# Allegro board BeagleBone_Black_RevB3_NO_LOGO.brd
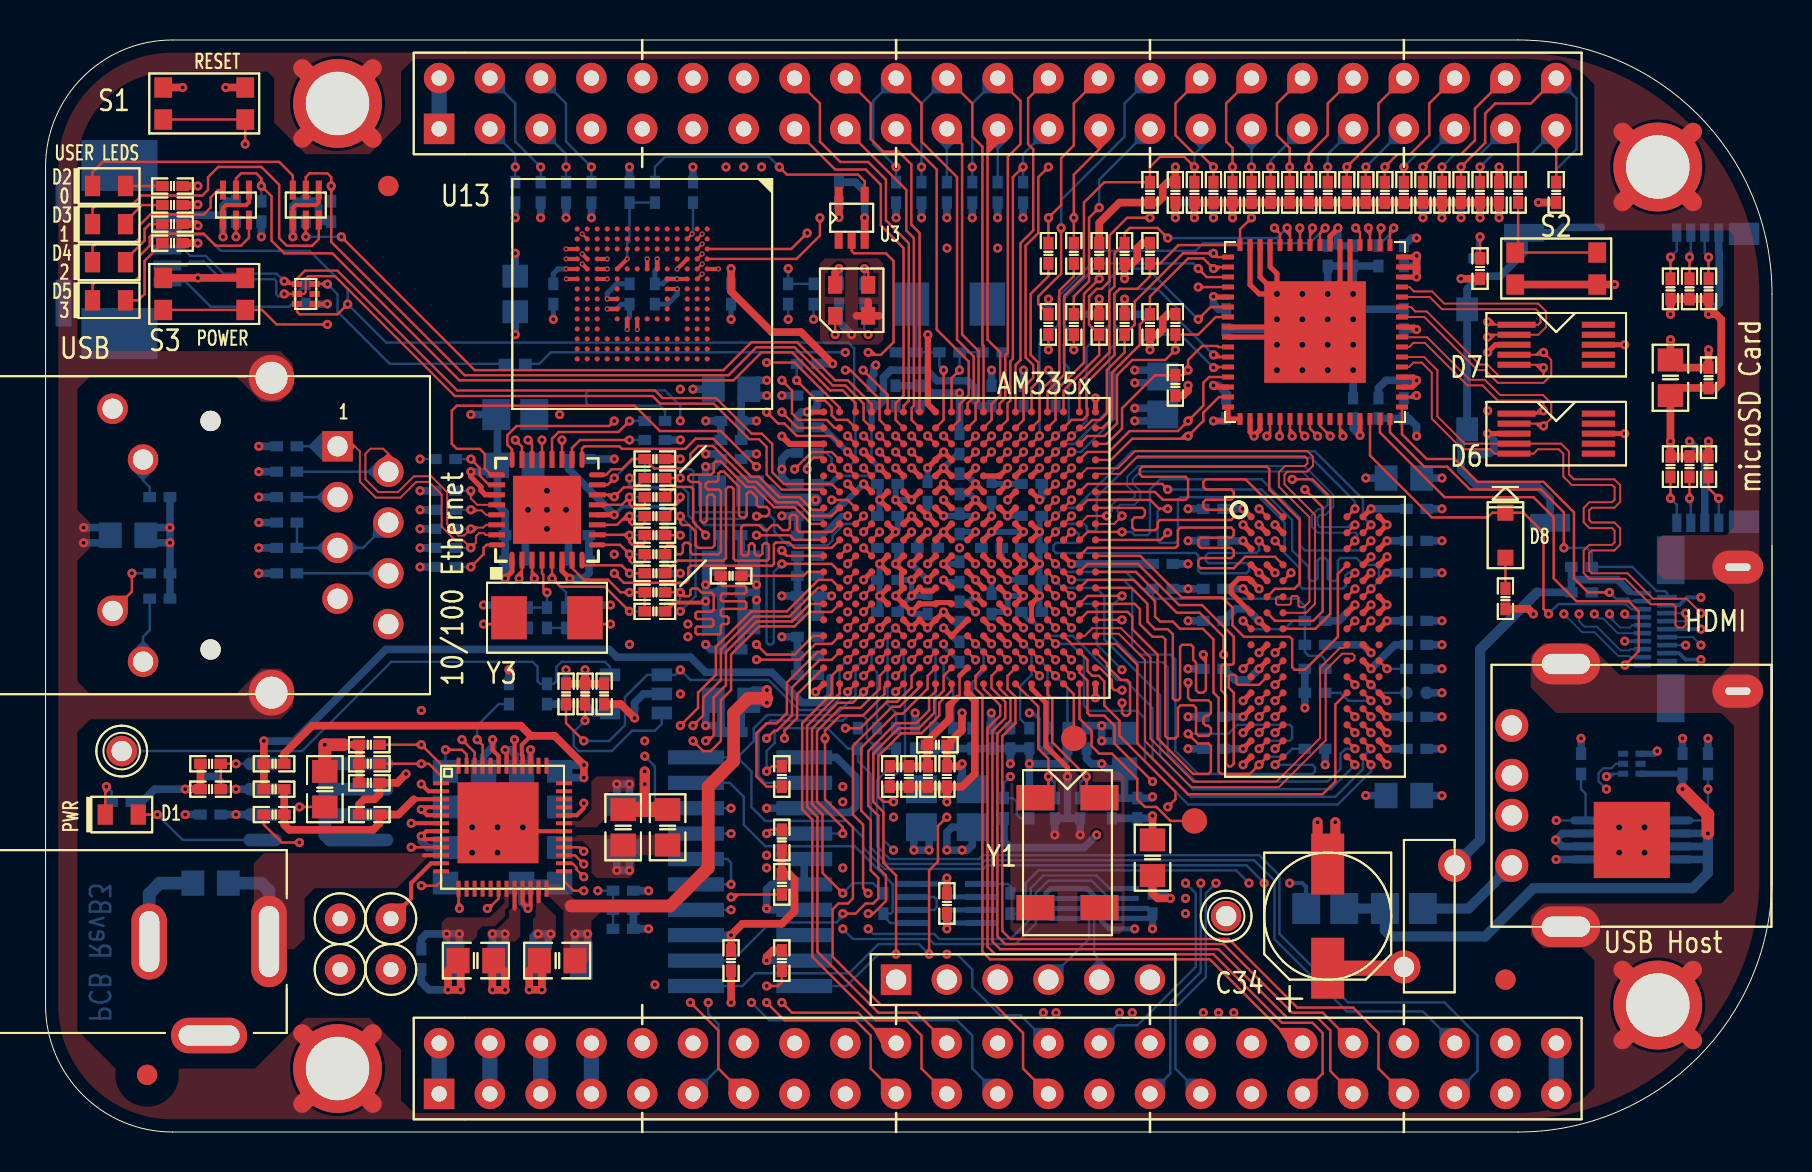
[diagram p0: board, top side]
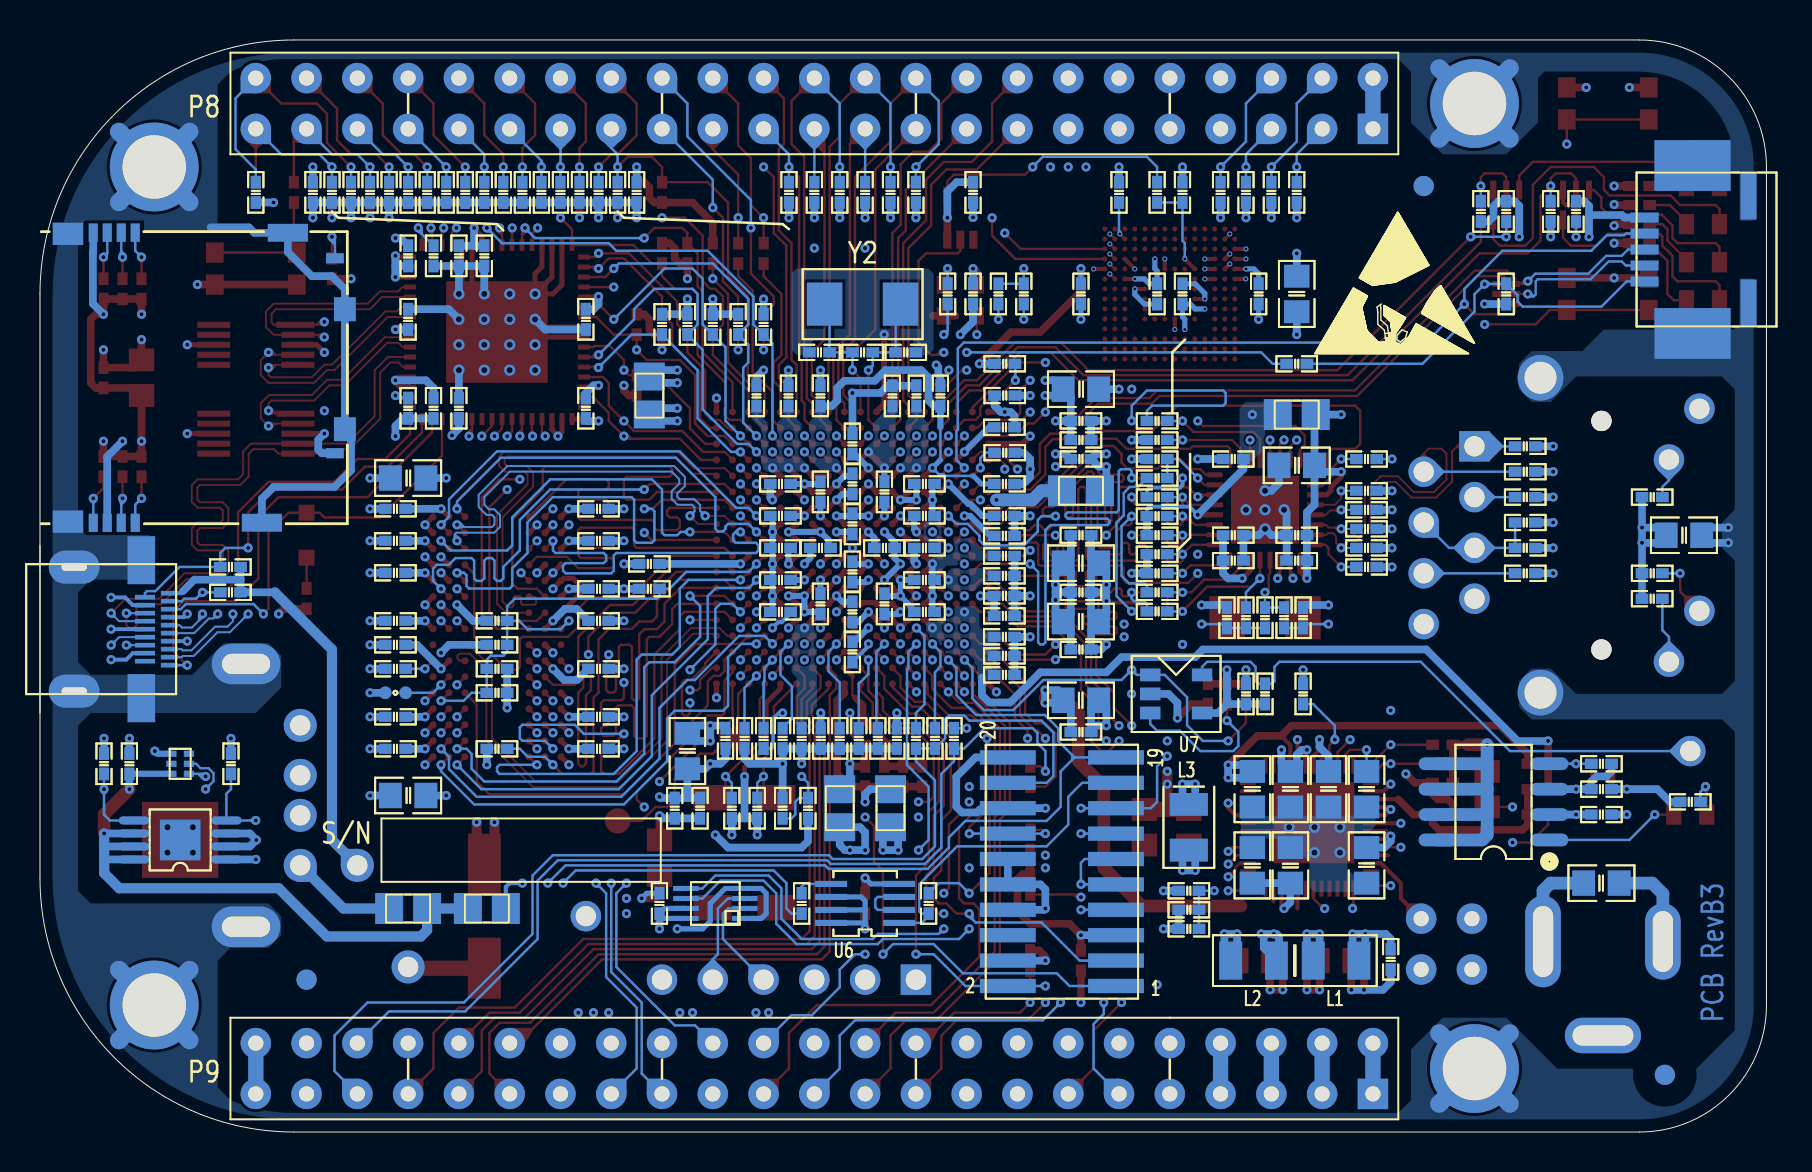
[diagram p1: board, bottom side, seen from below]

Outline 86.36 x 54.61 mm; copper layers: TOP, LYR2_GND, LYR3, LYR4, LYR5_PWR, BOTTOM. Coordinates in mm from the lower left corner of the outline.
Outline path: 0,48.26 0,6.35 arc(1.86,1.86) 6.35,0 73.66,0 arc(82.64,3.72) 86.36,12.7 86.36,41.91 arc(82.64,50.89) 73.66,54.61 6.35,54.61 arc(1.86,52.75) 0,48.26

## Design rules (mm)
net group HDMI_TX0: nets HDMI_TX0+ HDMI_TX0-
net group HDMI_TX1: nets HDMI_TX1+ HDMI_TX1-
net group HDMI_TX2: nets HDMI_TX2+ HDMI_TX2-
net group HDMI_TXC: nets HDMI_TXC+ HDMI_TXC-
net group RX: nets RXN RXP
net group TX: nets TXN TXP
net group USB0: nets USB0_DM USB0_DP
net group USB1: nets USB1_DM USB1_DP
net group CLK: nets MMC0_CLKO
net group DDR_ADD: nets DDR_A0 DDR_A1 DDR_A2 DDR_A3 DDR_A4 DDR_A5 DDR_A6 DDR_A7 DDR_A8 DDR_A9 DDR_A10 DDR_A11 DDR_A12 DDR_A13 DDR_A14 DDR_BA0 DDR_BA1 DDR_BA2 DDR_CASN DDR_CKE DDR_CLK DDR_CLKN DDR_CSN DDR_ODT DDR_RASN DDR_WEN
net group DDR_DQ0: nets DDR_D0 DDR_D1 DDR_D2 DDR_D3 DDR_D4 DDR_D5 DDR_D6 DDR_D7 DDR_DQM0 DDR_DQS0 DDR_DQSN0
net group DDR_DQ1: nets DDR_D8 DDR_D9 DDR_D10 DDR_D11 DDR_D12 DDR_D13 DDR_D14 DDR_D15 DDR_DQM1 DDR_DQS1 DDR_DQSN1
nets with their own width: min track width 0.203; nets USB1_VBUS

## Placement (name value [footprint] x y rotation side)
C1  10uF,10V  [805]  13.97 17.14 270 top
C2  10uF,10V  [805]  8.26 12.45 0 bottom
C3  0.1uf,6.3V  [402]  16.19 19.37 0 top
C4  10uF,10V  [805]  20 17.14 90 bottom
C7  10uF,10V  [805]  23.81 13.34 270 bottom
C8  10uF,10V  [805]  25.72 13.34 270 bottom
C9  10uF,10V  [805]  21.53 8.57 180 top
C10  10uF,10V  [805]  20 13.34 90 bottom
C11  10uF,10V  [805]  28.89 15.24 270 top
C12  10uF,10V  [805]  25.59 8.57 0 top
C13  10uF,10V  [805]  23.81 17.14 90 bottom
C14  10uF,10V  [805]  25.72 17.14 90 bottom
C15  10uF,10V  [805]  21.91 17.14 90 bottom
C16  2.2uF,6.3V  [402]  16.19 17.46 180 top
C17  2.2uF,6.3V  [402]  8.26 15.88 180 bottom
C18  2.2uF,6.3V  [402]  16.19 18.41 180 top
C19  470pF,6.3V  [402]  8.26 18.41 180 top
C20  0.1uf,6.3V  [402]  8.26 17.14 180 bottom
C21  18pF,50V  [402]  50.48 16.19 90 bottom
C22  18pF,50V  [402]  51.75 16.19 90 bottom
C24  1uF,10V  [402]  28.89 11.11 0 bottom
C25  18pF,50V  [402]  47.37 38.99 0 bottom
C26  18pF,50V  [402]  43.05 38.99 180 bottom
C27  0.1uf,6.3V  [402]  45.09 11.43 90 top
C28  0.1uf,6.3V  [402]  55.88 27.17 0 bottom
C29  0.1uf,6.3V  [402]  34.29 8.57 270 top
C30  0.1uf,6.3V  [402]  28.89 10.16 0 bottom
C31  0.1uf,6.3V  [402]  43.18 17.78 270 top
C32  0.001uf,50V  [402]  42.23 17.78 270 top
C33  0.1uf,6.3V  [402]  44.13 17.78 270 top
C34  100uF,6.3V  [RD205SMD_250D]  64.14 10.79 90 top
C35  0.1uf,6.3V  [402]  81.89 18.41 90 bottom
C36  0.1uf,6.3V  [402]  13.02 41.91 270 bottom
C37  0.1uf,6.3V  [402]  27.94 21.91 270 top
C38  0.1uf,6.3V  [402]  34.29 34.61 180 bottom
C39  10uF,10V  [805]  34.29 25.53 0 bottom
C40  10uF,10V  [805]  34.29 28.45 0 bottom
C41  0.1uf,6.3V  [402]  42.12 32.41 180 bottom
C42  0.1uf,6.3V  [402]  45.72 32.41 270 bottom
C43  0.1uf,6.3V  [402]  47.32 32.01 90 bottom
C44  0.1uf,6.3V  [402]  38.12 25.81 180 bottom
C45  0.1uf,6.3V  [402]  38.12 29.81 180 bottom
C46  0.1uf,6.3V  [402]  44.12 29.21 0 bottom
C47  0.1uf,6.3V  [402]  45.72 30.41 270 bottom
C48  0.1uf,6.3V  [402]  47.32 29.21 0 bottom
C49  0.1uf,6.3V  [402]  45.72 28.01 90 bottom
C50  0.1uf,6.3V  [402]  47.32 26.41 90 bottom
C51  0.1uf,6.3V  [402]  34.29 29.84 180 bottom
C52  0.1uf,6.3V  [402]  34.29 26.99 180 bottom
C53  0.1uf,6.3V  [402]  34.29 24.13 180 bottom
C54  0.1uf,6.3V  [402]  38.12 26.81 180 bottom
C55  10uF,10V  [805]  31.11 15.24 270 top
C56  0.1uf,6.3V  [402]  45.72 34.41 270 bottom
C57  0.1uf,6.3V  [402]  56.52 46.99 270 top
C58  0.1uf,6.3V  [402]  42.52 36.81 90 bottom
C59  0.1uf,6.3V  [402]  43.5 19.68 270 bottom
C60  0.1uf,6.3V  [402]  42.12 27.61 180 bottom
C61  0.1uf,6.3V  [402]  72.71 46.99 270 top
C62  10uF,10V  [805]  34.29 21.59 0 bottom
C63  0.1uf,6.3V  [402]  44.12 26.41 90 bottom
C64  0.1uf,6.3V  [402]  34.29 20 180 bottom
C65  0.1uf,6.3V  [402]  42.12 29.21 180 bottom
C66  0.1uf,6.3V  [402]  42.12 30.81 180 bottom
C67  0.1uf,6.3V  [402]  34.29 35.56 180 bottom
C68  0.1uf,6.3V  [402]  48.92 36.81 270 bottom
C69  0.1uf,6.3V  [402]  38.12 28.81 0 bottom
C70  0.1uf,6.3V  [402]  42.12 26.01 180 bottom
C71  0.1uf,6.3V  [402]  38.1 36.83 180 bottom
C72  0.1uf,6.3V  [402]  45.72 26.01 270 bottom
C73  0.1uf,6.3V  [402]  49.32 32.41 0 bottom
C74  0.1uf,6.3V  [402]  50.52 36.81 270 bottom
C75  0.1uf,6.3V  [402]  56.52 46.99 270 bottom
C76  0.1uf,6.3V  [402]  72.71 46.99 270 bottom
C77  10uF,10V  [805]  34.29 37.15 180 bottom
C78  0.1uf,6.3V  [402]  34.29 33.66 0 bottom
C79  0.1uf,6.3V  [402]  38.12 27.81 180 bottom
C80  0.1uf,6.3V  [402]  41.32 36.81 90 bottom
C81  0.1uf,6.3V  [402]  47.32 36.81 90 bottom
C82  0.1uf,6.3V  [402]  38.12 24.77 180 bottom
C83  0.1uf,6.3V  [402]  38.12 23.81 180 bottom
C84  0.1uf,6.3V  [402]  38.12 32.41 180 bottom
C85  0.1uf,6.3V  [402]  38.12 22.86 180 bottom
C86  0.1uf,6.3V  [402]  38.12 35.24 180 bottom
C87  0.1uf,6.3V  [402]  38.12 30.81 180 bottom
C88  0.1uf,6.3V  [402]  45.72 24.01 270 bottom
C89  1uF,10V  [402]  46.35 19.68 270 bottom
C90  1uF,10V  [402]  44.45 19.68 270 bottom
C91  1uF,10V  [402]  45.4 19.68 270 bottom
C92  0.1uf,6.3V  [402]  48.26 19.68 270 bottom
C93  0.1uf,6.3V  [402]  45.09 17.78 270 top
C94  0.1uf,6.3V  [402]  44.12 32.01 270 bottom
C95  10uF,10V  [805]  53.98 19.05 90 bottom
C96  10uF,10V  [805]  55.37 13.72 90 top
C97  0.1uf,6.3V  [402]  49.32 30.81 180 bottom
C98  0.1uf,6.3V  [402]  49.32 29.21 180 bottom
C99  0.1uf,6.3V  [402]  49.32 27.61 180 bottom
C100  0.1uf,6.3V  [402]  49.32 26.01 180 bottom
C101  0.1uf,6.3V  [402]  52.07 19.68 270 bottom
C102  0.1uf,6.3V  [402]  53.34 16.19 90 bottom
C103  0.1uf,6.3V  [402]  54.61 16.19 90 bottom
C104  1uF,10V  [402]  49.21 19.68 270 bottom
C105  0.1uf,6.3V  [402]  47.31 19.68 270 bottom
C106  0.1uf,6.3V  [402]  43.72 36.81 90 bottom
C107  0.1uf,6.3V  [402]  58.42 31.17 180 bottom
C108  0.1uf,6.3V  [402]  58.42 29.57 180 bottom
C109  0.1uf,6.3V  [402]  58.42 27.17 180 bottom
C110  0.1uf,6.3V  [402]  58.42 25.57 180 bottom
C111  0.1uf,6.3V  [402]  58.42 23.16 180 bottom
C112  0.1uf,6.3V  [402]  58.42 20.76 180 bottom
C113  0.1uf,6.3V  [402]  58.42 19.16 180 bottom
C114  0.1uf,6.3V  [402]  68.58 31.17 0 bottom
C115  0.1uf,6.3V  [402]  68.58 29.57 0 bottom
C116  0.1uf,6.3V  [402]  68.58 27.97 0 bottom
C117  0.1uf,6.3V  [402]  68.58 25.57 0 bottom
C118  10uF,10V  [805]  67.94 32.7 180 bottom
C119  0.1uf,6.3V  [402]  68.58 24.36 0 bottom
C120  0.1uf,6.3V  [402]  68.58 20.76 0 bottom
C121  0.1uf,6.3V  [402]  68.58 19.16 0 bottom
C122  10uF,10V  [805]  67.94 16.83 180 bottom
C123  0.001uf,50V  [402]  63.5 24.36 0 bottom
C124  0.1uf,6.3V  [402]  63.5 21.96 180 bottom
C125  2.2uF,6.3V  [402]  32.38 46.99 90 bottom
C126  10uF,10V  [805]  23.5 41.91 90 bottom
C127  0.1uf,6.3V  [402]  25.4 41.91 270 bottom
C128  0.1uf,6.3V  [402]  29.21 41.91 90 bottom
C129  0.1uf,6.3V  [402]  30.48 41.91 270 bottom
C130  0.1uf,6.3V  [402]  34.29 41.91 270 bottom
C131  0.1uf,6.3V  [402]  23.5 28.57 0 bottom
C132  0.1uf,6.3V  [402]  23.5 29.84 0 bottom
C133  10uF,10V  [805]  23.5 33.34 180 bottom
C134  1uF,10V  [402]  26.67 28.57 180 bottom
C135  0.1uf,6.3V  [402]  26.67 33.66 0 bottom
C136  470pF,6.3V  [0402]  26.67 29.84 180 bottom
C137  15pF,DNI  [402]  12.06 34.29 180 bottom
C138  15pF,DNI  [402]  12.06 33.02 180 bottom
C139  15pF,DNI  [402]  12.06 31.75 180 bottom
C140  15pF,DNI  [402]  12.06 27.94 180 bottom
C141  0.022uF,10V  [402]  12.06 30.48 180 bottom
C142  30pF,50V  [402]  23.18 25.72 90 bottom
C143  30pF,50V  [402]  26.99 25.72 90 bottom
C144  2.2uF,6.3V  [402]  59.05 40.64 270 bottom
C145  0.1uf,6.3V  [402]  59.05 36.2 270 bottom
C146  2.2uF,6.3V  [402]  64.14 43.81 270 bottom
C147  0.1uf,6.3V  [402]  65.41 36.2 90 bottom
C148  2.2uF,6.3V  [402]  65.41 43.81 270 bottom
C149  0.1uf,6.3V  [402]  67.94 43.81 90 bottom
C150  0.1uf,6.3V  [402]  67.94 40.64 90 bottom
C151  2.2uF,6.3V  [402]  66.67 36.2 270 bottom
C152  0.1uf,6.3V  [402]  26.04 21.91 90 bottom
C153  10uF,10V  [805]  81.28 37.72 90 top
C154  0.1uf,6.3V  [402]  83.19 37.72 90 top
C155  0.1uf,6.3V  [402]  55.37 11.43 270 bottom
C156  47pf,6.3V  [402]  55.24 43.94 90 top
C157  47pf,6.3V  [402]  53.98 40.39 90 top
C158  0.1uf,6.3V  [402]  39.69 46.99 90 bottom
C159  0.1uf,6.3V  [402]  39.69 41.91 270 bottom
C160  47pf,6.3V  [402]  55.24 40.39 270 top
C161  47pf,6.3V  [402]  51.44 40.39 90 bottom
C162  47pf,6.3V  [402]  52.7 40.39 90 bottom
C163  47pf,6.3V  [402]  56.52 40.39 90 top
C164  47pf,6.3V  [402]  50.16 40.39 90 bottom
C165  47pf,6.3V  [402]  55.24 46.99 270 top
C166  47pf,6.3V  [402]  52.7 40.39 90 top
C167  47pf,6.3V  [402]  53.98 43.94 270 top
C168  47pf,6.3V  [402]  52.7 43.94 90 top
C169  47pf,6.3V  [402]  56.52 37.34 270 top
C170  47pf,6.3V  [402]  53.98 40.39 90 bottom
C171  47pf,6.3V  [402]  75.56 46.99 270 bottom
C172  47pf,6.3V  [402]  55.24 40.39 90 bottom
C173  47pf,6.3V  [402]  75.56 46.99 270 top
D1  LTST-C191TBKT  [LED_0603]  3.81 15.88 0 top
D2  LTST-C191TBKT  [LED_0603]  3.17 47.31 0 top
D3  LTST-C191TBKT  [LED_0603]  3.17 45.4 0 top
D4  LTST-C191TBKT  [LED_0603]  3.17 43.5 0 top
D5  LTST-C191TBKT  [LED_0603]  3.17 41.59 0 top
D6  IP4283CZ10-TT  [TSSOP10]  75.56 34.92 270 top
D7  IP4283CZ10-TT  [TSSOP10]  75.56 39.37 270 top
D8  RB751V40,115  [SOD323]  73.03 29.84 90 top
FB1  150OHM800mA  [SM-7351-IND-0805]  34.29 32.07 0 bottom
FB2  150OHM800mA  [SM-7351-IND-0805]  46.35 16.19 270 bottom
FB3  150OHM800mA  [SM-7351-IND-0805]  43.81 16.19 270 bottom
FB4  150OHM800mA  [SM-7351-IND-0805]  23.5 35.88 180 bottom
FB5  150OHM800mA  [SM-7351-IND-0805]  55.88 36.83 270 bottom
FB7  150OHM800mA  [SM-7351-IND-0805]  67.94 11.18 0 bottom
FB8  150OHM800mA  [SM-7351-IND-0805]  64.01 11.18 0 bottom
J1  HEADER 6  [SIP6]  42.55 7.62 90 top
L1  LQM2HPN2R2MG0L  [2520]  21.53 8.57 180 bottom
L2  LQM2HPN2R2MG0L  [2520]  25.65 8.57 0 bottom
L3  LQM2HPN2R2MG0L  [2520]  28.89 15.24 270 bottom
MTG1  MHOLE  [MTGH200C125D_PL]  14.61 3.17 90 top
MTG2  MHOLE  [MTGH200C125D_PL]  80.64 6.35 90 top
MTG3  MHOLE  [MTGH200C125D_PL]  14.61 51.44 90 top
MTG4  MHOLE  [MTGH200C125D_PL]  80.64 48.26 90 top
NOREF  -  []  85.72 28.57 0 top
NOREF#2  -  [unnamed#2]  17.14 47.31 270 top
NOREF#3  -  []  0 0 0 top
NOREF#4  -  []  86.36 39.69 0 top
NOREF#5  -  [unnamed#2]  5.08 2.86 270 top
NOREF#6  -  []  86.36 12.7 0 top
NOREF#7  -  [unnamed#2]  73.03 7.62 270 top
NOREF#8  -  []  319.53 -174.24 0 top
NOREF#9  -  []  80.64 48.26 0 top
NOREF#10  -  []  85.72 39.05 0 top
NOREF#11  -  []  80.64 6.35 0 top
NOREF#12  -  []  85.72 28.57 0 top
NOREF#13  -  []  81.92 52.07 0 top
NOREF#14  -  []  -11.96 0 90 top
NOREF#15  -  []  14.61 3.17 0 top
NOREF#16  -  []  86.36 27.94 0 top
NOREF#17  -  []  -368.3 -256.54 0 top
NOREF#18  -  []  6.35 54.61 0 top
NOREF#19  -  []  14.61 3.17 0 top
NOREF#20  -  []  0 -11.96 0 top
NOREF#21  -  []  -368.17 -256.47 0 top
NOREF#22  -  []  80.64 6.35 0 top
NOREF#23  -  []  -34.92 -47.62 0 top
NOREF#24  -  []  0 0 0 top
NOREF#25  -  []  14.61 51.44 0 top
NOREF#26  -  []  1.91 53.34 180 bottom
NOREF#27  -  [unnamed#2]  5.08 2.86 270 bottom
NOREF#28  -  [unnamed#2]  73.03 7.62 270 bottom
NOREF#29  -  [unnamed#2]  17.14 47.31 270 bottom
P1  PJ-200A  [CONN3-PWR-PJ102A]  11.18 9.53 180 top
P2  CTI JTAG,DNI  [HEADER10X2_SMD]  35.24 13.02 90 bottom
P3  USB-A Conn. - 87520-xx1xx  [USB_A_SH]  73.34 13.34 90 top
P4  USB5MINI  [USB5MINI_4SHIELDED_SMD-5]  6.1 44.13 0 bottom
P5  WE_7499010211A  [RJ45-7499010211A]  14.61 34.29 270 top
P6  microHDMI  [CONN19_HDMI]  84.65 25.15 270 bottom
P8  FEMALE HEADER 2x23  [HEADER23X2]  19.68 50.16 0 top
P9  FEMALE HEADER 2x23  [HEADER23X2]  19.68 1.91 0 top
P10  SCHA5B0200  [SD-MICRO-SCHA5B0300]  81.6 37.72 270 bottom
Q1  DMC56404  [SMINI6-F3-B]  13.02 46.35 180 top
Q2  DMC56404  [SMINI6-F3-B]  9.53 46.35 180 top
R1  100K,1%  [402]  23.18 21.91 270 bottom
R3  1.5K,5%  [402]  26.04 21.91 270 top
R4  1.5K,5%  [402]  26.99 21.91 270 top
R5  0  [402]  16.19 15.88 180 top
R6  0  [402]  18.8 8.64 270 bottom
R7  0  [402]  11.43 15.88 180 top
R8  0  [402]  11.43 17.14 180 top
R9  0,DNI  [402]  11.43 18.41 0 top
R10  470K,1%  [402]  8.26 17.14 180 top
R11  280K,1%  [402]  8.26 18.41 0 bottom
R12  820,5%  [402]  3.81 16.51 180 bottom
R14  10K,1%  [402]  28.89 12.06 180 bottom
R17  1M,1%  [402]  45.21 38.99 180 bottom
R18  33  [0402]  41.91 11.43 270 bottom
R19  0,1%  [402]  41.59 19.68 270 bottom
R20  0,1%  [402]  42.55 19.68 90 bottom
R21  33  [0402]  48.26 11.43 270 bottom
R22  49.9,1%  [402]  55.88 28.41 180 bottom
R23  4.75K,1%  [402]  36.83 12.38 270 top
R24  4.75K,1%  [402]  36.83 14.61 90 top
R25  4.75K,1%  [402]  36.83 8.57 90 top
R26  4.75K,1%  [402]  50.16 19.68 90 bottom
R27  0,1%  [402]  44.61 19.37 180 top
R28  33  [0402]  34.29 27.81 180 top
R45  33  [0402]  50.16 43.94 90 top
R46  33  [0402]  51.44 43.94 90 top
R47  33  [0402]  51.44 40.39 90 top
R48  33  [0402]  50.16 40.39 90 top
R49  0,1%  [402]  38.1 33.97 0 bottom
R50  0,1%  [402]  36.83 17.78 270 top
R51  0,1%  [402]  40.64 19.68 90 bottom
R52  10K,1%  [402]  83.16 18.41 270 bottom
R53  10K,1%  [402]  76.81 18.41 90 bottom
R54  10K,1%  [402]  51.12 19.68 90 bottom
R55  100K,1%,DNI  [402]  58.42 46.99 90 bottom
R56  100K,1%  [402]  57.47 46.99 90 bottom
R57  100K,1%,DNI  [402]  60.33 46.99 90 bottom
R58  100K,1%,DNI  [402]  61.28 46.99 90 bottom
R59  100K,1%,DNI  [402]  59.37 46.99 90 bottom
R60  100K,1%,DNI  [402]  62.23 46.99 90 bottom
R61  100K,1%,DNI  [402]  63.18 46.99 90 bottom
R62  100K,1%,DNI  [402]  64.14 46.99 90 bottom
R63  100K,1%,DNI  [402]  65.09 46.99 90 bottom
R64  100K,1%,DNI  [402]  66.04 46.99 90 bottom
R65  100K,1%  [402]  66.99 46.99 90 bottom
R66  100K,1%  [402]  67.94 46.99 90 bottom
R67  100K,1%  [402]  68.9 46.99 90 bottom
R68  100K,1%  [402]  69.85 46.99 90 bottom
R69  100K,1%,DNI  [402]  70.8 46.99 90 bottom
R70  100K,1%,DNI  [402]  71.75 46.99 90 bottom
R71  820,5%  [402]  6.35 44.45 180 top
R72  820,5%  [402]  6.35 47.31 180 top
R73  820,5%  [402]  6.35 46.35 180 top
R74  820,5%  [402]  6.35 45.4 180 top
R75  100  [402]  73.66 46.99 270 top
R76  100K,1%  [402]  13.02 46.04 90 bottom
R77  100K,1%  [402]  14.29 46.04 270 bottom
R78  100K,1%  [402]  9.53 46.04 90 bottom
R79  100K,1%  [402]  10.79 46.04 270 bottom
R80  100K,1%  [402]  58.42 46.99 270 top
R81  100K,1%,DNI  [402]  57.47 46.99 270 top
R82  100K,1%  [402]  60.33 46.99 270 top
R83  100K,1%  [402]  61.28 46.99 270 top
R84  100K,1%  [402]  59.37 46.99 270 top
R85  100K,1%  [402]  62.23 46.99 270 top
R86  100K,1%  [402]  63.18 46.99 270 top
R87  100K,1%  [402]  64.14 46.99 270 top
R88  100K,1%  [402]  65.09 46.99 270 top
R89  100K,1%  [402]  66.04 46.99 270 top
R90  100K,1%,DNI  [402]  66.99 46.99 270 top
R91  100K,1%,DNI  [402]  67.94 46.99 270 top
R92  100K,1%,DNI  [402]  68.9 46.99 270 top
R93  100K,1%,DNI  [402]  69.85 46.99 270 top
R94  100K,1%  [402]  70.8 46.99 270 top
R95  100K,1%  [402]  71.75 46.99 270 top
R96  10K,1%  [402]  68.58 23.16 180 bottom
R97  1.5K,1%  [402]  63.5 19.16 180 bottom
R98  10K,1%  [402]  63.5 25.57 180 bottom
R99  240E  [SM-7351-RES-0402]  68.58 21.96 180 bottom
R100  10K,1%  [402]  63.5 23.16 180 bottom
R101  10K,1%  [402]  48.9 46.99 90 bottom
R102  10K,1%  [402]  46.35 46.99 90 bottom
R103  10K,1%  [402]  26.04 46.99 90 bottom
R104  10K,1%  [402]  27.3 46.99 90 bottom
R105  10K,1%  [402]  47.62 46.99 90 bottom
R106  10K,1%  [402]  43.81 46.99 90 bottom
R107  10K,1%  [402]  23.5 46.99 90 bottom
R108  10K,1%  [402]  24.77 46.99 90 bottom
R109  10K,1%  [402]  42.55 46.99 90 bottom
R110  10K,1%  [402]  45.09 46.99 90 bottom
R111  10K,1%  [402]  29.21 46.99 270 bottom
R112  1.5K,1%  [402]  30.48 30.8 0 bottom
R113  1.5K,1%  [402]  30.48 33.66 0 bottom
R114  1.5K,1%  [402]  30.48 29.84 0 bottom
R115  10K,1%  [402]  30.48 31.75 0 bottom
R116  10K,1%  [402]  30.48 27.94 0 bottom
R117  10K,1%  [402]  30.48 28.89 0 bottom
R118  10K,1%  [402]  30.48 26.04 0 top
R119  1.5K,5%  [402]  30.48 33.66 180 top
R120  49.9,1%  [402]  20 29.21 180 bottom
R121  49.9,1%  [402]  20 30.16 180 bottom
R122  49.9,1%  [402]  20 31.11 180 bottom
R123  49.9,1%  [402]  20 32.07 180 bottom
R124  10,1%,DNI  [402]  30.48 26.99 180 top
R125  100,1%  [402]  30.48 27.94 180 top
R126  100,1%  [402]  30.48 28.89 180 top
R127  100,1%  [402]  30.48 29.84 180 top
R128  100,1%  [402]  30.48 30.8 180 top
R129  100,1%  [402]  20 33.66 0 bottom
R130  470,5%  [402]  5.71 27.94 180 bottom
R131  100,1%  [402]  30.48 26.99 180 bottom
R132  470,5%  [402]  5.71 31.75 180 bottom
R133  100,1%  [402]  30.48 31.75 180 top
R134  100,1%  [402]  30.48 35.56 180 bottom
R135  10K,1%  [402]  5.71 26.67 0 bottom
R136  .1,0805  [805]  4.13 29.84 180 bottom
R137  0,1%  [402]  12.06 29.21 180 bottom
R138  100,1%  [402]  30.48 32.7 180 bottom
R139  100,1%  [402]  30.48 32.7 180 top
R140  0,1%,DNI  [402]  30.48 26.04 180 bottom
R141  1M,1%,DNI  [402]  25.08 25.72 270 bottom
R142  0,1%  [402]  26.04 25.72 90 bottom
R143  10,1%  [402]  24.13 25.72 270 bottom
R144  12.1K,1%  [402]  20 28.26 180 bottom
R145  10K,1%  [402]  30.48 34.61 0 bottom
R146  1.5K,5%  [402]  76.83 26.99 0 bottom
R147  1.5K,5%  [402]  76.83 28.26 0 bottom
R148  10K,1%  [402]  67.94 36.2 270 bottom
R149  0,1%  [402]  66.67 43.81 270 bottom
R150  10K,1%  [402]  81.28 42.16 90 top
R151  10K,1%  [402]  83.19 42.16 90 top
R152  10K,1%  [402]  83.19 33.27 270 top
R153  10K,1%  [402]  82.23 33.27 270 top
R154  10K,1%  [402]  81.28 33.27 270 top
R155  10K,1%  [402]  82.23 42.16 90 top
R156  10K,1%  [402]  25.08 21.91 90 bottom
R157  10K,1%  [402]  71.75 43.18 270 top
R158  10K,1%  [402]  38.1 38.42 180 bottom
R159  0,1%  [402]  23.5 38.42 0 bottom
R160  0,1%  [402]  38.42 41.91 90 bottom
R161  0,1%  [402]  37.15 41.91 90 bottom
R162  0,1%  [402]  30.48 46.99 270 bottom
R163  4.75K,1%  [402]  47.94 16.19 90 bottom
R164  4.75K,1%  [402]  49.21 16.19 90 bottom
R166  27K,1%  [402]  73.03 26.67 270 top
R167  33  [0402]  40.96 41.91 270 bottom
RT1  PTC_RXEF010  [POLYSW200-5638-310]  70.48 13.34 90 top
S1  KMR231GLFS  [SW4SMD_63X161LS]  7.94 51.44 180 top
S2  KMR231GLFS  [SW4SMD_63X161LS]  75.56 43.18 180 top
S3  KMR231GLFS  [SW4SMD_63X161LS]  7.94 41.91 180 top
TP1  TESTPT1  [TP1-8040]  59.05 10.79 0 top
TP2  TESTPT1  [TP60C_SMD]  57.47 15.56 0 top
TP3  TESTPT1  [TP60C_SMD]  51.44 19.68 0 top
TP4  TESTPT1  [TP1-8040]  3.81 19.05 0 top
TP5  TESTPT1  [TP60C33D]  14.73 10.67 0 top
TP6  TESTPT1  [TP60C33D]  14.73 8.13 0 top
TP7  TESTPT1  [TP60C33D]  17.27 10.67 0 top
TP8  TESTPT1  [TP60C33D]  17.27 8.13 0 top
U2  TPS65217C  [U_48_RSL]  22.86 15.24 0 top
U3  SN74LVC1G06DCK  [DCK5_2P15X1P4]  40.32 45.72 0 top
U4  TL5209  [SO8-25X75]  13.65 16.51 90 bottom
U5  AM3358_ZCZ_ES1.0  [AM33XX_15X15]  45.72 29.21 180 top
U6  SN74AUC1G74  [SOP8_DCT]  45.09 11.43 90 bottom
U7  24LC32A  [SOT23-5]  29.53 21.91 270 bottom
U8  TPS2051 (DGN)  [DGN-16X60]  79.35 14.61 90 bottom
U9  TPD4S012  [U_6_DRY]  79.35 18.41 90 bottom
U10  TPD4S012  [U_6_DRY]  13.02 41.91 270 top
U11  TDA19988  [QFN64S9X9P5]  63.5 40.01 0 top
U12  MT41K256M16HA -125:E  [BGA96_T9_P8_9X14]  63.5 24.77 0 top
U13  MEM_MNAND_2GB  [BGA153_P14_P5_11P5X13]  29.84 41.91 270 top
U14  LAN8710A  [QFN32_5X5MM_EP3P3MM]  25.08 31.11 0 top
U15  SN74LVC2G241  [U_8_DCU]  52.58 11.43 90 bottom
Y1  32.768KHz MC-306  [XTAL4_126-216SMD]  51.12 13.97 270 top
Y2  24MHz  [XTAL150SMD_125X196]  45.21 41.4 0 bottom
Y3  25.000MHz  [XTAL150SMD_125X196]  25.08 25.72 180 top
Y4  24.576MHZ  [OSC4_61X65LS_79X98SMD]  40.32 41.59 0 top

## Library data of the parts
C1 C2 C4 C7-C15 C39 C40 C55 C62 C77 C95 C96 C118 C122 C126 C133 C153 = CAP_10uF_Y5V_10V_10%_0805
C3 C20 C27-C31 C33 C35-C38 C41-C54 C56-C61 C63-C76 C78-C88 C92-C94 C97-C103 C105-C117 C119-C121 C124 C127-C132 C135 C145 C147 C149 C150 C152 C154-C173 = CAP_0.1uF_X5R_6.3V_20% 0201
C16-C18 C125 C144 C146 C148 C151 = CAP_2.2uF_X5R_6.3V_10%_0402
C19 = CAP_470PF_X7R_25V_10%_0402
C21 C22 C25 C26 = CAP_18PF_COG_50V_5%_0402
C24 C89-C91 C104 C134 = CAP_1.0UF_X5R_10V_10%_0402
C32 C123 = CAP_0.001_X7R_50V_5%_0402
C34 = CAP_100UF_TANT_6.3V_3528-21
C136 = 470pF/5%/50V/C0G/0603_0
C137-C140 = CAP_0402_100pF_COG_50V
C141 = CAP_0402_0.1uf_X5R_10V
C142 C143 = CAP_30PF_COG_50V_5%_0402
D1-D5 = LED_LTST-C150GKT_0
D6 D7 = 32CTQ030/TO_1
D8 = DIO_SR305_TH_0
FB1-FB4 FB7 FB8 = FER_180_200_0
FB5 = FER_180_200_0805
J1 = HEADER 6: User Part Number: ***
L1-L3 = IND_2.2uH_2.6A_10%_SMD
MTG1-MTG4 = MHOLE
P1 = Power_Jack: Tolerance: X; User Part Number: X
P2 = HDR_10x2_CJTAG_0
P3 = CONN_54819-0578_2: User Part Number: PART#; Tolerance: TOL
P4 = MINI-USB-AB-SOCKET
P5 = CONN_RJ45_MAG_WE_0
P6 = CONN_HDMI_TYPED: Tolerance: TOL*; User Part Number: PRT#
P8 P9 = HDR_46_F_2_0.1_0.1
P10 = microSD_CONN_8: User Part Number: X; Tolerance: X
Q1 Q2 = RN1907
R1 R55-R70 R75-R95 = RES_100K_1/16W_1%_0402
R3 R4 R119 R146 R147 = RES_1.5K_1/16W_5%_0402
R5-R9 R23-R26 R50 R51 R112-R118 R159-R164 = RES_4.75K_1/16W_1%_0402
R10 R12 R71-R74 R130 R132 = RES_470_1/10W_5%_0402
R11 = RES_470_1/10W_5%_0402: signal model: 33OHMRESISTOR1_16W5_0402_SM_735_33
R14 = RES_10K_1/16W_1%_0402: signal model: 33OHMRESISTOR1_16W5_0402_SM_735_33
R17 = RES_1M_1/16W_1%_0402: signal model: 33OHMRESISTOR1_16W5_0402_SM_735_33
R18 R21 R47 = RES_33_0402: signal model: 33OHMRESISTOR1_16W5_0402_SM_735_33
R19 R27 R140 R142 R149 R156 = RES_0_1/16W_1%_0402
R20 = RES_0_1/16W_1%_0402: signal model: 33OHMRESISTOR1_16W5_0402_SM_735_33
R22 R120-R123 = RES_4.7K_0402
R28 R45 R46 R48 R167 = RES_33_0402
R49 = RES_100K_1/16W_1%_0402: signal model: 33OHMRESISTOR1_16W5_0402_SM_735_33
R52-R54 R96-R98 R100-R111 R135 R137 R143 R145 R148 R150-R155 R157 R158 = RES_10K_1/16W_1%_0402
R99 = Res
R124-R126 R129 R134 R138 = 100-1/10W-1%-0603_4
R127 R128 R131 R133 R139 = RES_100_1/10W_5%_0402
R136 = RES_0.1_0805
R141 = RES_1M_1/16W_1%_0402
R144 = RES_12.1K_1/16W_1%_0402
R166 = RES_22.6K_1/16W_1%_0402
RT1 = PTC_RXEF010: User Part Number: X; Tolerance: X
S1 S3 = SW_KT11P2JM_2
S2 = SW_KT11P2JM_1
TP1-TP8 = TESTPT1
U2 = PWR_TPS65217_2
U3 = IC_SN74LVC1G06DCK_0
U4 = PWR_TLV70233DBV_0: Tolerance: X; User Part Number: X
U5 = IC_AM335X_ZCZ
U6 = IC_SN74AUC1G74
U7 = MEM_24LC32_SOT23-5
U8 = TPS2061_1: User Part Number: X; Tolerance: X
U9 U10 = PROT_TPD4S012
U11 = IC_TDA19988_HVQFN64_5
U12 = MT47H256M8_7
U13 = MEM_MNAND_2GB
U14 = LAN8710 QFN32_1
U15 = IC_SN74LVC2G241_1
Y1 = CRYS_32_768KHz_SMD32_1
Y2 = CRYS_24MHz_SCC_0
Y3 = Suntsu ITEMP 25MHz _0.005% 20pf
Y4 = OSC_12MHz_1.3V: Tolerance: TOL*; User Part Number: P/N*

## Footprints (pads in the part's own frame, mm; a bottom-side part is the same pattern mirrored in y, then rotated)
0402
  rect 0.635x0.508 smd: 1(-0.508,0) 2(0.508,0)
402
  rect 0.635x0.508 smd: 1(-0.508,0) 2(0.508,0)
805
  rect 1.143x1.27 smd: 1(-0.889,0) 2(0.889,0)
2520
  rect 1.143x1.905 smd: 1(-1.143,0) 2(1.143,0)
AM33XX_15X15
  round 0.356 smd: A1(-6.8,6.8) A2(-6,6.8) A3(-5.2,6.8) A4(-4.4,6.8) A5(-3.6,6.8) A6(-2.8,6.8) A7(-2,6.8) A8(-1.2,6.8) A9(-0.4,6.8) A10(0.4,6.8) A11(1.2,6.8) A12(2,6.8) A13(2.8,6.8) A14(3.6,6.8) A15(4.4,6.8) A16(5.2,6.8) A17(6,6.8) A18(6.8,6.8) B1(-6.8,6) B2(-6,6) B3(-5.2,6) B4(-4.4,6) B5(-3.6,6) B6(-2.8,6) B7(-2,6) B8(-1.2,6) B9(-0.4,6) B10(0.4,6) B11(1.2,6) B12(2,6) B13(2.8,6) B14(3.6,6) B15(4.4,6) B16(5.2,6) B17(6,6) B18(6.8,6) C1(-6.8,5.2) C2(-6,5.2) C3(-5.2,5.2) C4(-4.4,5.2) C5(-3.6,5.2) C6(-2.8,5.2) C7(-2,5.2) C8(-1.2,5.2) C9(-0.4,5.2) C10(0.4,5.2) C11(1.2,5.2) C12(2,5.2) C13(2.8,5.2) C14(3.6,5.2) C15(4.4,5.2) C16(5.2,5.2) C17(6,5.2) C18(6.8,5.2) D1(-6.8,4.4) D2(-6,4.4) D3(-5.2,4.4) D4(-4.4,4.4) D5(-3.6,4.4) D6(-2.8,4.4) D7(-2,4.4) D8(-1.2,4.4) D9(-0.4,4.4) D10(0.4,4.4) D11(1.2,4.4) D12(2,4.4) D13(2.8,4.4) D14(3.6,4.4) D15(4.4,4.4) D16(5.2,4.4) D17(6,4.4) D18(6.8,4.4) E1(-6.8,3.6) E2(-6,3.6) E3(-5.2,3.6) E4(-4.4,3.6) E5(-3.6,3.6) E6(-2.8,3.6) E7(-2,3.6) E8(-1.2,3.6) E9(-0.4,3.6) E10(0.4,3.6) E11(1.2,3.6) E12(2,3.6) E13(2.8,3.6) E14(3.6,3.6) E15(4.4,3.6) E16(5.2,3.6) E17(6,3.6) E18(6.8,3.6) F1(-6.8,2.8) F2(-6,2.8) F3(-5.2,2.8) F4(-4.4,2.8) F5(-3.6,2.8) F6(-2.8,2.8) F7(-2,2.8) F8(-1.2,2.8) F9(-0.4,2.8) F10(0.4,2.8) F11(1.2,2.8) F12(2,2.8) F13(2.8,2.8) F14(3.6,2.8) F15(4.4,2.8) F16(5.2,2.8) F17(6,2.8) F18(6.8,2.8) G1(-6.8,2) G2(-6,2) G3(-5.2,2) G4(-4.4,2) G5(-3.6,2) G6(-2.8,2) G7(-2,2) G8(-1.2,2) G9(-0.4,2) G10(0.4,2) G11(1.2,2) G12(2,2) G13(2.8,2) G14(3.6,2) G15(4.4,2) G16(5.2,2) G17(6,2) G18(6.8,2) H1(-6.8,1.2) H2(-6,1.2) H3(-5.2,1.2) H4(-4.4,1.2) H5(-3.6,1.2) H6(-2.8,1.2) H7(-2,1.2) H8(-1.2,1.2) H9(-0.4,1.2) H10(0.4,1.2) H11(1.2,1.2) H12(2,1.2) H13(2.8,1.2) H14(3.6,1.2) H15(4.4,1.2) H16(5.2,1.2) H17(6,1.2) H18(6.8,1.2) J1(-6.8,0.4) J2(-6,0.4) J3(-5.2,0.4) J4(-4.4,0.4) J5(-3.6,0.4) J6(-2.8,0.4) J7(-2,0.4) J8(-1.2,0.4) J9(-0.4,0.4) J10(0.4,0.4) J11(1.2,0.4) J12(2,0.4) J13(2.8,0.4) J14(3.6,0.4) J15(4.4,0.4) J16(5.2,0.4) J17(6,0.4) J18(6.8,0.4) K1(-6.8,-0.4) K2(-6,-0.4) K3(-5.2,-0.4) K4(-4.4,-0.4) K5(-3.6,-0.4) K6(-2.8,-0.4) K7(-2,-0.4) K8(-1.2,-0.4) K9(-0.4,-0.4) K10(0.4,-0.4) K11(1.2,-0.4) K12(2,-0.4) K13(2.8,-0.4) K14(3.6,-0.4) K15(4.4,-0.4) K16(5.2,-0.4) K17(6,-0.4) K18(6.8,-0.4) L1(-6.8,-1.2) L2(-6,-1.2) L3(-5.2,-1.2) L4(-4.4,-1.2) L5(-3.6,-1.2) L6(-2.8,-1.2) L7(-2,-1.2) L8(-1.2,-1.2) L9(-0.4,-1.2) L10(0.4,-1.2) L11(1.2,-1.2) L12(2,-1.2) L13(2.8,-1.2) L14(3.6,-1.2) L15(4.4,-1.2) L16(5.2,-1.2) L17(6,-1.2) L18(6.8,-1.2) M1(-6.8,-2) M2(-6,-2) M3(-5.2,-2) M4(-4.4,-2) M5(-3.6,-2) M6(-2.8,-2) M7(-2,-2) M8(-1.2,-2) M9(-0.4,-2) M10(0.4,-2) M11(1.2,-2) M12(2,-2) M13(2.8,-2) M14(3.6,-2) M15(4.4,-2) M16(5.2,-2) M17(6,-2) M18(6.8,-2) N1(-6.8,-2.8) N2(-6,-2.8) N3(-5.2,-2.8) N4(-4.4,-2.8) N5(-3.6,-2.8) N6(-2.8,-2.8) N7(-2,-2.8) N8(-1.2,-2.8) N9(-0.4,-2.8) N10(0.4,-2.8) N11(1.2,-2.8) N12(2,-2.8) N13(2.8,-2.8) N14(3.6,-2.8) N15(4.4,-2.8) N16(5.2,-2.8) N17(6,-2.8) N18(6.8,-2.8) P1(-6.8,-3.6) P2(-6,-3.6) P3(-5.2,-3.6) P4(-4.4,-3.6) P5(-3.6,-3.6) P6(-2.8,-3.6) P7(-2,-3.6) P8(-1.2,-3.6) P9(-0.4,-3.6) P10(0.4,-3.6) P11(1.2,-3.6) P12(2,-3.6) P13(2.8,-3.6) P14(3.6,-3.6) P15(4.4,-3.6) P16(5.2,-3.6) P17(6,-3.6) P18(6.8,-3.6) R1(-6.8,-4.4) R2(-6,-4.4) R3(-5.2,-4.4) R4(-4.4,-4.4) R5(-3.6,-4.4) R6(-2.8,-4.4) R7(-2,-4.4) R8(-1.2,-4.4) R9(-0.4,-4.4) R10(0.4,-4.4) R11(1.2,-4.4) R12(2,-4.4) R13(2.8,-4.4) R14(3.6,-4.4) R15(4.4,-4.4) R16(5.2,-4.4) R17(6,-4.4) R18(6.8,-4.4) T1(-6.8,-5.2) T2(-6,-5.2) T3(-5.2,-5.2) T4(-4.4,-5.2) T5(-3.6,-5.2) T6(-2.8,-5.2) T7(-2,-5.2) T8(-1.2,-5.2) T9(-0.4,-5.2) T10(0.4,-5.2) T11(1.2,-5.2) T12(2,-5.2) T13(2.8,-5.2) T14(3.6,-5.2) T15(4.4,-5.2) T16(5.2,-5.2) T17(6,-5.2) T18(6.8,-5.2) U1(-6.8,-6) U2(-6,-6) U3(-5.2,-6) U4(-4.4,-6) U5(-3.6,-6) U6(-2.8,-6) U7(-2,-6) U8(-1.2,-6) U9(-0.4,-6) U10(0.4,-6) U11(1.2,-6) U12(2,-6) U13(2.8,-6) U14(3.6,-6) U15(4.4,-6) U16(5.2,-6) U17(6,-6) U18(6.8,-6) V1(-6.8,-6.8) V2(-6,-6.8) V3(-5.2,-6.8) V4(-4.4,-6.8) V5(-3.6,-6.8) V6(-2.8,-6.8) V7(-2,-6.8) V8(-1.2,-6.8) V9(-0.4,-6.8) V10(0.4,-6.8) V11(1.2,-6.8) V12(2,-6.8) V13(2.8,-6.8) V14(3.6,-6.8) V15(4.4,-6.8) V16(5.2,-6.8) V17(6,-6.8) V18(6.8,-6.8)
BGA96_T9_P8_9X14
  round 0.356 smd: A1(-3.2,6.001) A2(-2.4,6.001) A3(-1.6,6.001) A7(1.6,6.001) A8(2.4,6.001) A9(3.2,6.001) B1(-3.2,5.201) B2(-2.4,5.201) B3(-1.6,5.201) B7(1.6,5.201) B8(2.4,5.201) B9(3.2,5.201) C1(-3.2,4.401) C2(-2.4,4.401) C3(-1.6,4.401) C7(1.6,4.401) C8(2.4,4.401) C9(3.2,4.401) D1(-3.2,3.6) D2(-2.4,3.6) D3(-1.6,3.6) D7(1.6,3.6) D8(2.4,3.6) D9(3.2,3.6) E1(-3.2,2.8) E2(-2.4,2.8) E3(-1.6,2.8) E7(1.6,2.8) E8(2.4,2.8) E9(3.2,2.8) F1(-3.2,2) F2(-2.4,2) F3(-1.6,2) F7(1.6,2) F8(2.4,2) F9(3.2,2) G1(-3.2,1.2) G2(-2.4,1.2) G3(-1.6,1.2) G7(1.6,1.2) G8(2.4,1.2) G9(3.2,1.2) H1(-3.2,0.4) H2(-2.4,0.4) H3(-1.6,0.4) H7(1.6,0.4) H8(2.4,0.4) H9(3.2,0.4) J1(-3.2,-0.4) J2(-2.4,-0.4) J3(-1.6,-0.4) J7(1.6,-0.4) J8(2.4,-0.4) J9(3.2,-0.4) K1(-3.2,-1.2) K2(-2.4,-1.2) K3(-1.6,-1.2) K7(1.6,-1.2) K8(2.4,-1.2) K9(3.2,-1.2) L1(-3.2,-2) L2(-2.4,-2) L3(-1.6,-2) L7(1.6,-2) L8(2.4,-2) L9(3.2,-2) M1(-3.2,-2.8) M2(-2.4,-2.8) M3(-1.6,-2.8) M7(1.6,-2.8) M8(2.4,-2.8) M9(3.2,-2.8) N1(-3.2,-3.6) N2(-2.4,-3.6) N3(-1.6,-3.6) N7(1.6,-3.6) N8(2.4,-3.6) N9(3.2,-3.6) P1(-3.2,-4.401) P2(-2.4,-4.401) P3(-1.6,-4.401) P7(1.6,-4.401) P8(2.4,-4.401) P9(3.2,-4.401) R1(-3.2,-5.201) R2(-2.4,-5.201) R3(-1.6,-5.201) R7(1.6,-5.201) R8(2.4,-5.201) R9(3.2,-5.201) T1(-3.2,-6.001) T2(-2.4,-6.001) T3(-1.6,-6.001) T7(1.6,-6.001) T8(2.4,-6.001) T9(3.2,-6.001)
BGA153_P14_P5_11P5X13
  round 0.254 smd: A1(-3.25,3.25) A2(-2.75,3.25) A3(-2.25,3.25) A4(-1.75,3.25) A5(-1.25,3.25) A6(-0.75,3.25) A7(-0.25,3.25) A8(0.25,3.25) A9(0.75,3.25) A10(1.25,3.25) A11(1.75,3.25) A12(2.25,3.25) A13(2.75,3.25) A14(3.25,3.25) B1(-3.25,2.75) B2(-2.75,2.75) B3(-2.25,2.75) B4(-1.75,2.75) B5(-1.25,2.75) B6(-0.75,2.75) B7(-0.25,2.75) B8(0.25,2.75) B9(0.75,2.75) B10(1.25,2.75) B11(1.75,2.75) B12(2.25,2.75) B13(2.75,2.75) B14(3.25,2.75) C1(-3.25,2.25) C2(-2.75,2.25) C3(-2.25,2.25) C4(-1.75,2.25) C5(-1.25,2.25) C6(-0.75,2.25) C7(-0.25,2.25) C8(0.25,2.25) C9(0.75,2.25) C10(1.25,2.25) C11(1.75,2.25) C12(2.25,2.25) C13(2.75,2.25) C14(3.25,2.25) D1(-3.25,1.75) D2(-2.75,1.75) D3(-2.25,1.75) D4(-1.75,1.75) D12(2.25,1.75) D13(2.75,1.75) D14(3.25,1.75) E1(-3.25,1.25) E2(-2.75,1.25) E3(-2.25,1.25) E5(-1.25,1.25) E6(-0.75,1.25) E7(-0.25,1.25) E8(0.25,1.25) E9(0.75,1.25) E10(1.25,1.25) E12(2.25,1.25) E13(2.75,1.25) E14(3.25,1.25) F1(-3.25,0.75) F2(-2.75,0.75) F3(-2.25,0.75) F5(-1.25,0.75) F10(1.25,0.75) F12(2.25,0.75) F13(2.75,0.75) F14(3.25,0.75) G1(-3.25,0.25) G2(-2.75,0.25) G3(-2.25,0.25) G5(-1.25,0.25) G10(1.25,0.25) G12(2.25,0.25) G13(2.75,0.25) G14(3.25,0.25) H1(-3.25,-0.25) H2(-2.75,-0.25) H3(-2.25,-0.25) H5(-1.25,-0.25) H10(1.25,-0.25) H12(2.25,-0.25) H13(2.75,-0.25) H14(3.25,-0.25) J1(-3.25,-0.75) J2(-2.75,-0.75) J3(-2.25,-0.75) J5(-1.25,-0.75) J10(1.25,-0.75) J12(2.25,-0.75) J13(2.75,-0.75) J14(3.25,-0.75) K1(-3.25,-1.25) K2(-2.75,-1.25) K3(-2.25,-1.25) K5(-1.25,-1.25) K6(-0.75,-1.25) K7(-0.25,-1.25) K8(0.25,-1.25) K9(0.75,-1.25) K10(1.25,-1.25) K12(2.25,-1.25) K13(2.75,-1.25) K14(3.25,-1.25) L1(-3.25,-1.75) L2(-2.75,-1.75) L3(-2.25,-1.75) L12(2.25,-1.75) L13(2.75,-1.75) L14(3.25,-1.75) M1(-3.25,-2.25) M2(-2.75,-2.25) M3(-2.25,-2.25) M4(-1.75,-2.25) M5(-1.25,-2.25) M6(-0.75,-2.25) M7(-0.25,-2.25) M8(0.25,-2.25) M9(0.75,-2.25) M10(1.25,-2.25) M11(1.75,-2.25) M12(2.25,-2.25) M13(2.75,-2.25) M14(3.25,-2.25) N1(-3.25,-2.75) N2(-2.75,-2.75) N3(-2.25,-2.75) N4(-1.75,-2.75) N5(-1.25,-2.75) N6(-0.75,-2.75) N7(-0.25,-2.75) N8(0.25,-2.75) N9(0.75,-2.75) N10(1.25,-2.75) N11(1.75,-2.75) N12(2.25,-2.75) N13(2.75,-2.75) N14(3.25,-2.75) P1(-3.25,-3.25) P2(-2.75,-3.25) P3(-2.25,-3.25) P4(-1.75,-3.25) P5(-1.25,-3.25) P6(-0.75,-3.25) P7(-0.25,-3.25) P8(0.25,-3.25) P9(0.75,-3.25) P10(1.25,-3.25) P11(1.75,-3.25) P12(2.25,-3.25) P13(2.75,-3.25) P14(3.25,-3.25)
CONN3-PWR-PJ102A
  oval 1.778x4.572 hole 1.016x3.556: 1(0,0)
  oval 1.778x3.81 hole 1.016x3.048: 2(5.994,0)
  oval 3.81x1.778 hole 3.048x1.016: 3(2.997,4.699)
CONN19_HDMI
  rect 0.23x0.85 smd: 1(1.8,4.765) 3(1.4,4.765) 5(1,4.765) 7(0.6,4.765) 9(0.2,4.765) 11(-0.2,4.765) 13(-0.6,4.765) 15(-1,4.765) 17(-1.4,4.765) 19(-1.8,4.765)
  rect 0.23x1 smd: 2(1.6,3.54) 4(1.2,3.54) 6(0.8,3.54) 8(0.4,3.54) 10(0,3.54) 12(-0.4,3.54) 14(-0.8,3.54) 16(-1.2,3.54) 18(-1.6,3.54)
  oval 1.651x2.54 hole 0.381x1.27: 20(3.1,0) 21(-3.1,0)
  rect 2.4x1.38 smd: 22(3.45,3.36) 23(-3.45,3.36)
DCK5_2P15X1P4
  rect 0.4x0.9 smd: 1(-0.65,-1.1) 2(0,-1.1) 3(0.65,-1.1) 4(0.65,1.1) 5(-0.65,1.1)
DGN-16X60
  oval 0.406x1.524 smd: 1(-0.975,-2.311) 2(-0.325,-2.311) 3(0.325,-2.311) 4(0.975,-2.311) 5(0.975,2.311) 6(0.325,2.311) 7(-0.325,2.311) 8(-0.975,2.311)
  rect 2.032x2.032 smd: 9(0,0)
HEADER10X2_SMD
  rect 0.711x2.794 smd: 1(-5.715,-2.705) 2(-5.715,2.705) 3(-4.445,-2.705) 4(-4.445,2.705) 5(-3.175,-2.705) 6(-3.175,2.705) 7(-1.905,-2.705) 8(-1.905,2.705) 9(-0.635,-2.705) 10(-0.635,2.705) 11(0.635,-2.705) 12(0.635,2.705) 13(1.905,-2.705) 14(1.905,2.705) 15(3.175,-2.705) 16(3.175,2.705) 17(4.445,-2.705) 18(4.445,2.705) 19(5.715,-2.705) 20(5.715,2.705)
HEADER23X2
  rect 1.524x1.524 hole 0.762: 1(0,0)
  round 1.524 hole 0.762: 2(0,2.54) 3(2.54,0) 4(2.54,2.54) 5(5.08,0) 6(5.08,2.54) 7(7.62,0) 8(7.62,2.54) 9(10.16,0) 10(10.16,2.54) 11(12.7,0) 12(12.7,2.54) 13(15.24,0) 14(15.24,2.54) 15(17.78,0) 16(17.78,2.54) 17(20.32,0) 18(20.32,2.54) 19(22.86,0) 20(22.86,2.54) 21(25.4,0) 22(25.4,2.54) 23(27.94,0) 24(27.94,2.54) 25(30.48,0) 26(30.48,2.54) 27(33.02,0) 28(33.02,2.54) 29(35.56,0) 30(35.56,2.54) 31(38.1,0) 32(38.1,2.54) 33(40.64,0) 34(40.64,2.54) 35(43.18,0) 36(43.18,2.54) 37(45.72,0) 38(45.72,2.54) 39(48.26,0) 40(48.26,2.54) 41(50.8,0) 42(50.8,2.54) 43(53.34,0) 44(53.34,2.54) 45(55.88,0) 46(55.88,2.54)
LED_0603
  rect 0.762x1.016 smd: 1(-0.826,0) 2(0.826,0)
MTGH200C125D_PL
  round 4.445 hole 3.175: 1(0,0)
OSC4_61X65LS_79X98SMD
  rect 0.711x0.889 smd: 1(-0.826,-0.775) 2(0.826,-0.775) 3(0.826,0.775) 4(-0.826,0.775)
POLYSW200-5638-310
  round 1.651 hole 1.016: 1(-5.08,2.54) 2(0,0)
QFN32_5X5MM_EP3P3MM
  oval 0.254x0.838 smd: 1(-1.751,-2.515) 8(1.751,-2.515) 17(1.751,2.515) 24(-1.751,2.515)
  rect 0.254x0.838 smd: 2(-1.251,-2.515) 3(-0.751,-2.515) 4(-0.25,-2.515) 5(0.25,-2.515) 6(0.751,-2.515) 7(1.251,-2.515) 18(1.251,2.515) 19(0.751,2.515) 20(0.25,2.515) 21(-0.25,2.515) 22(-0.751,2.515) 23(-1.251,2.515)
  oval 0.838x0.254 smd: 9(2.515,-1.751) 16(2.515,1.751) 25(-2.515,1.751) 32(-2.515,-1.751)
  rect 0.838x0.254 smd: 10(2.515,-1.251) 11(2.515,-0.751) 12(2.515,-0.25) 13(2.515,0.25) 14(2.515,0.751) 15(2.515,1.251) 26(-2.515,1.251) 27(-2.515,0.751) 28(-2.515,0.25) 29(-2.515,-0.25) 30(-2.515,-0.751) 31(-2.515,-1.251)
  rect 3.404x3.404 smd: 33(0,0)
QFN64S9X9P5
  rect 0.6x0.25 smd: 1(-4.35,3.75) 2(-4.35,3.25) 3(-4.35,2.75) 4(-4.35,2.25) 5(-4.35,1.75) 6(-4.35,1.25) 7(-4.35,0.75) 8(-4.35,0.25) 9(-4.35,-0.25) 10(-4.35,-0.75) 11(-4.35,-1.25) 12(-4.35,-1.75) 13(-4.35,-2.25) 14(-4.35,-2.75) 15(-4.35,-3.25) 16(-4.35,-3.75) 33(4.35,-3.75) 34(4.35,-3.25) 35(4.35,-2.75) 36(4.35,-2.25) 37(4.35,-1.75) 38(4.35,-1.25) 39(4.35,-0.75) 40(4.35,-0.25) 41(4.35,0.25) 42(4.35,0.75) 43(4.35,1.25) 44(4.35,1.75) 45(4.35,2.25) 46(4.35,2.75) 47(4.35,3.25) 48(4.35,3.75)
  rect 0.25x0.6 smd: 17(-3.75,-4.35) 18(-3.25,-4.35) 19(-2.75,-4.35) 20(-2.25,-4.35) 21(-1.75,-4.35) 22(-1.25,-4.35) 23(-0.75,-4.35) 24(-0.25,-4.35) 25(0.25,-4.35) 26(0.75,-4.35) 27(1.25,-4.35) 28(1.75,-4.35) 29(2.25,-4.35) 30(2.75,-4.35) 31(3.25,-4.35) 32(3.75,-4.35) 49(3.75,4.35) 50(3.25,4.35) 51(2.75,4.35) 52(2.25,4.35) 53(1.75,4.35) 54(1.25,4.35) 55(0.75,4.35) 56(0.25,4.35) 57(-0.25,4.35) 58(-0.75,4.35) 59(-1.25,4.35) 60(-1.75,4.35) 61(-2.25,4.35) 62(-2.75,4.35) 63(-3.25,4.35) 64(-3.75,4.35)
  rect 5.08x5.08 smd: 65(0,0)
RD205SMD_250D
  rect 3.048x1.651 smd: 1(-2.603,0) 2(2.603,0)
RJ45-7499010211A
  round 1.016 hole 3.251 unplated: (-1.27,-6.35) (10.16,-6.35)
  rect 1.524x1.524 hole 1.016: 1(0,0)
  round 1.524 hole 1.016: 2(1.27,2.54) 3(2.54,0) 4(3.81,2.54) 5(5.08,0) 6(6.35,2.54) 7(7.62,0) 8(8.89,2.54) 9(-1.88,-11.252) 10(0.66,-9.728) 11(8.23,-11.252) 12(10.77,-9.728)
  round 2.286 hole 1.6: 13(-3.429,-3.302) 14(12.319,-3.302)
SD-MICRO-SCHA5B0300
  rect 0.914x0.457 smd: 1(-7.257,0) 2(-7.257,-0.7) 3(-7.257,-1.4) 4(-7.257,-2.1) 5(7.257,-2.1) 6(7.257,-1.4) 7(7.257,-0.7) 8(7.257,0)
  rect 0.508x0.889 smd: 9(3.775,9.989) 10(-5.975,9.989)
  rect 0.889x2.007 smd: 11(-7.25,7.635) 12(7.25,6.335)
  rect 1.118x1.524 smd: 13(-7.196,-3.365) 14(7.196,-3.365)
  rect 1.194x1.092 smd: 15(-3.425,10.488) 16(2.575,10.488)
SIP6
  rect 1.524x1.524 hole 1.016: 1(0,0)
  round 1.524 hole 1.016: 2(0,-2.54) 3(0,-5.08) 4(0,-7.62) 5(0,-10.16) 6(0,-12.7)
SM-7351-IND-0805
  rect 1.397x1.549 smd: 1(-0.95,0) 2(0.95,0)
SM-7351-RES-0402
  round 0.635 smd: 1(-0.508,0) 2(0.508,0)
SMINI6-F3-B
  rect 0.305x0.95 smd: 1(0.65,0.75) 2(0,0.75) 3(-0.65,0.75) 4(-0.65,-0.75) 5(0,-0.75) 6(0.65,-0.75)
SO8-25X75
  oval 0.635x1.905 smd: 1(-1.905,-2.794) 2(-0.635,-2.794) 3(0.635,-2.794) 4(1.905,-2.794) 5(1.905,2.794) 6(0.635,2.794) 7(-0.635,2.794) 8(-1.905,2.794)
SOD323
  rect 0.8x0.8 smd: 1(1.125,0) 2(-1.125,0)
SOP8_DCT
  rect 0.305x1.6 smd: 1(-0.975,-1.702) 2(-0.325,-1.702) 3(0.325,-1.702) 4(0.975,-1.702) 5(0.975,1.702) 6(0.325,1.702) 7(-0.325,1.702) 8(-0.975,1.702)
SOT23-5
  rect 0.635x1.016 smd: 1(-0.953,-1.295) 2(0,-1.295) 3(0.953,-1.295) 4(0.953,1.295) 5(-0.953,1.295)
SW4SMD_63X161LS
  rect 0.889x1.016 smd: 1(-2.05,-0.8) 2(-2.05,0.8) 3(2.05,-0.8) 4(2.05,0.8)
TP1-8040
  round 1.524 hole 1.016: 1(0,0)
TP60C33D
  round 1.524 hole 0.762: 1(0,0)
TP60C_SMD
  round 1.27 smd: 1(0,0)
TSSOP10
  rect 0.305x1.905 smd: 1(-1,-1.981)
  rect 0.305x1.651 smd: 2(-0.5,-2.108) 3(0,-2.108) 4(0.5,-2.108) 5(1,-2.108) 6(1,2.108) 7(0.5,2.108) 8(0,2.108) 9(-0.5,2.108) 10(-1,2.108)
U_6_DRY
  rect 0.305x0.508 smd: 1(-0.5,-0.439) 2(0,-0.439) 3(0.5,-0.439) 4(0.5,0.439) 5(0,0.439) 6(-0.5,0.439)
U_8_DCU
  rect 0.254x1.27 smd: 1(-0.749,-1.473) 2(-0.249,-1.473) 3(0.249,-1.473) 4(0.749,-1.473) 5(0.749,1.473) 6(0.249,1.473) 7(-0.249,1.473) 8(-0.749,1.473)
U_48_RSL
  rect 0.8x0.2 smd: 1(-3.075,2.2) 2(-3.075,1.8) 3(-3.075,1.4) 4(-3.075,1) 5(-3.075,0.6) 6(-3.075,0.2) 7(-3.075,-0.2) 8(-3.075,-0.6) 9(-3.075,-1) 10(-3.075,-1.4) 11(-3.075,-1.8) 12(-3.075,-2.2) 25(3.075,-2.2) 26(3.075,-1.8) 27(3.075,-1.4) 28(3.075,-1) 29(3.075,-0.6) 30(3.075,-0.2) 31(3.075,0.2) 32(3.075,0.6) 33(3.075,1) 34(3.075,1.4) 35(3.075,1.8) 36(3.075,2.2)
  rect 0.2x0.8 smd: 13(-2.2,-3.075) 14(-1.8,-3.075) 15(-1.4,-3.075) 16(-1,-3.075) 17(-0.6,-3.075) 18(-0.2,-3.075) 19(0.2,-3.075) 20(0.6,-3.075) 21(1,-3.075) 22(1.4,-3.075) 23(1.8,-3.075) 24(2.2,-3.075) 37(2.2,3.075) 38(1.8,3.075) 39(1.4,3.075) 40(1,3.075) 41(0.6,3.075) 42(0.2,3.075) 43(-0.2,3.075) 44(-0.6,3.075) 45(-1,3.075) 46(-1.4,3.075) 47(-1.8,3.075) 48(-2.2,3.075)
  rect 4.05x4.05 smd: 49(-0.225,0.225)
unnamed#2
  round 1.016 smd: 1(0,0)
USB5MINI_4SHIELDED_SMD-5
  rect 1.4x0.5 smd: 1(0,1.6) 2(0,0.8) 3(0,0) 4(0,-0.8) 5(0,-1.6)
  rect 3.81x2.54 smd: 6(-2.4,4.2) 7(-2.4,-4.2)
  rect 0.8x2.35 smd: 8(-5.2,2.675) 9(-5.2,-2.675)
USB_A_SH
  round 1.651 hole 1.016: 1(0,0) 2(2.499,0) 3(4.501,0) 4(7,0)
  oval 2.032x3.429 hole 1.016x2.413: 5(-3.071,-2.71) 6(10.071,-2.71)
XTAL4_126-216SMD
  rect 1.27x1.905 smd: 1(-2.748,-1.6) 2(2.751,-1.6) 3(2.751,1.6) 4(-2.748,1.6)
XTAL150SMD_125X196
  rect 1.778x2.159 smd: 1(-1.9,0) 2(1.9,0)

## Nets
DGND: C1.1 C2.1 C3.1 C4.1 C7.1 C8.1 C9.1 C10.1 C11.1 C12.1 C13.1 C14.1 C15.1 C16.2 C17.2 C18.2 C19.2 C20.2 C24.2 C27.2 C28.2 C29.2 C30.2 C34.2 C35.2 C36.2 C37.2 C38.2 C39.1 C40.1 C41.2 C42.2 C43.2 C44.2 C45.2 C46.2 C47.2 C48.2 C49.2 C50.2 C51.2 C52.2 C53.2 C54.2 C55.1 C56.1 C57.1 C58.2 C59.2 C60.1 C61.1 C62.1 C63.2 C64.2 C65.2 C66.2 C67.2 C68.1 C69.1 C70.1 C71.1 C72.1 C73.1 C74.1 C75.1 C76.1 C77.2 C78.2 C79.2 C80.2 C81.2 C82.2 C83.2 C84.2 C85.2 C86.2 C87.2 C88.2 C89.2 C90.2 C91.2 C92.2 C94.2 C95.1 C96.1 C97.2 C98.2 C99.2 C100.2 C101.2 C102.2 C103.2 C104.2 C105.2 C106.2 C107.2 C108.2 C109.2 C110.2 C111.2 C112.2 C113.2 C114.2 C115.2 C116.2 C117.2 C118.1 C119.2 C120.2 C121.2 C122.1 C123.2 C124.2 C125.2 C126.1 C127.2 C128.2 C129.2 C130.2 C131.2 C132.2 C133.1 C134.2 C135.2 C136.2 C137.2 C138.2 C139.2 C140.2 C141.2 C142.2 C143.2 C144.2 C145.2 C146.2 C147.2 C148.2 C149.2 C150.2 C151.2 C152.2 C153.2 C154.2 C155.1 C156.2 C157.2 C158.2 C159.2 C160.2 C161.2 C162.2 C163.2 C164.2 C165.2 C166.2 C167.2 C168.2 C169.2 C170.2 C171.2 C172.2 C173.2 D6.3 D6.8 D7.3 D7.8 FB3.2 J1.1 P1.2 P2.4(TDIS) P2.8(GND1) P2.10(GND2) P2.12(GND3) P2.16(GND4) P2.20(GND5) P3.4(P4) P4.5(G1) P5.8(GND) P6.4(DAT2_S) P6.7(DAT1_S) P6.10(DAT0_S) P6.13(CLK_S) P6.16(DDC/CEC GND) P8.1 P8.2(26) P9.1 P9.2(26) P9.43(22) P9.44(47) P9.45(23) P9.46(48) P10.6(VSS) P10.9(GND) Q1.1(4) Q1.4 Q2.1(4) Q2.4 R10.2 R12.1 R22.1 R25.2 R49.1 R53.2 R54.1 R76.2 R77.2 R78.2 R79.2 R80.2 R81.2 R82.2 R83.2 R84.2 R85.2 R86.2 R87.2 R88.2 R89.2 R90.2 R91.2 R92.2 R93.2 R94.2 R95.2 R96.1 R99.1 R100.2 R115.2 R116.2 R117.2 R118.2 R130.1 R132.1 R135.2 R136.1 R144.2 R145.2 R148.2 R149.2 R164.2 S1.1(A1) S1.3(A2) S2.2(B1) S2.4(B2) S3.1(A1) S3.3(A2) TP1.1(TP) TP8.1(TP) U2.30(PGND) U2.41(AGND) U2.49(PPAD) U3.3(GND) U4.5(GND1) U4.6(GND3) U4.7(GND2) U4.8(GND4) U5.A1(VSS1) U5.A18(VSS2) U5.F8(VSS3) U5.G8(VSS4) U5.G9(VSS5) U5.G11(VSS6) U5.G12(VSS7) U5.H6(VSS8) U5.H7(VSS9) U5.H8(VSS10) U5.H9(VSS11) U5.H10(VSS12) U5.H12(VSS13) U5.J6(VSS14) U5.J7(VSS15) U5.J8(VSS16) U5.J9(VSS17) U5.J10(VSS18) U5.J11(VSS19) U5.K7(VSS20) U5.K9(VSS21) U5.K10(VSS22) U5.K11(VSS23) U5.L10(VSS24) U5.L11(VSS25) U5.L12(VSS26) U5.L13(VSS27) U5.M6(VSS28) U5.M7(VSS29) U5.M8(VSS30) U5.M9(VSS31) U5.M10(VSS32) U5.M12(VSS33) U5.M14(VSSA_USB2) U5.N7(VSS34) U5.N10(VSS35) U5.N11(VSS36) U5.N14(VSSA_USB1) U5.V1(VSS37) U5.V18(VSS38) U6.4(GND) U7.2(VSS) U8.1(GND) U8.9(PAD) U9.4(GND) U10.4(GND) U11.8(VPB1) U11.9(VPB0) U11.16(VPC2) U11.17(VPC1) U11.18(VPC0) U11.19(VPP) U11.53(A0_I2C) U11.54(A1_I2C) U11.61(VPA2) U11.62(VPA1) U11.63(VPA0) U11.65(PAD) U12.A9(VSS1) U12.B1(VSSQ1) U12.B3(VSS2) U12.B9(VSSQ2) U12.D1(VSSQ3) U12.D8(VSSQ4) U12.E1(VSS3) U12.E2(VSSQ5) U12.E8(VSSQ6) U12.F9(VSSQ7) U12.G1(VSSQ8) U12.G8(VSS4) U12.G9(VSSQ9) U12.J2(VSS5) U12.J8(VSS6) U12.M1(VSS7) U12.M9(VSS8) U12.P1(VSS9) U12.P9(VSS10) U12.T1(VSS11) U12.T9(VSS12) U13.C4(VSSQ4) U13.E7(VSS2) U13.G5(VSS1) U13.H10(VSS3) U13.K8(VSS4) U13.N2(VSSQ1) U13.N5(VSS5) U13.P4(VSSQ3) U13.P6(VSSQ2) U14.33(GND_EP) U15.1(1\O\E\) U15.4(GND) Y4.2(GND)
GND_EARTH: MTG1.1(TP) MTG2.1(TP) MTG3.1(TP) MTG4.1(TP) P3.5(SHELD1) P3.6(PAD4) P4.6(G3) P4.7(G2) P4.8(G5) P4.9(G4) P5.13(SHD1) P5.14(SHD2) P6.20(MTG1) P6.21(MTG2) P6.22(MTG3) P6.23(MTG4) P10.11(GND3) P10.12(GND4) P10.13(GND5) P10.14(GND6) P10.15(GND7) P10.16(GND8) R136.2
GND_OSC0: C25.2 C26.2 U5.V11(VSS_OSC0)
GND_OSC1: C21.1 C22.1 U5.A5(VSS_RTC)
GNDA_ADC: C31.2 C32.2 C33.2 C93.2 FB3.1 P9.34(42) U5.A9(VREFN) U5.E8(VSSA_ADC)
VBUS: FB7.2 P3.1(P1)
VDD_1V8: C14.2 C78.1 C86.1 C88.1 FB1.1 FB2.2 FB5.2 R9.2 U2.40(LDO3) U5.D10(VDDS_SRAM_MPU_BB) U5.E9(VDDS_SRAM_CORE_BG) U5.N16(VDDA1P8V_USB0) U5.R16(VDDA1P8V_USB1)
VDD_3V3A: C15.2 C27.1 C37.1 C38.1 C56.2 C57.2 C58.1 C59.1 C60.2 C61.2 C66.1 C67.1 C68.2 C69.2 C70.2 C71.2 C72.2 C73.2 C74.2 C75.2 C76.2 C77.1 C87.1 C152.1 C158.1 C159.1 R1.1 R3.1 R4.1 R14.1 R52.1 R55.1 R56.1 R57.1 R58.1 R59.1 R60.1 R61.1 R62.1 R63.1 R64.1 R65.1 R66.1 R67.1 R68.1 R69.1 R70.1 R156.1 U2.43(LDO4) U3.5(VCC) U5.E10(VDDSHV61) U5.E11(VDDSHV62) U5.E12(VDDSHV63) U5.E13(VDDSHV64) U5.F14(VDDSHV65) U5.G14(VDDSHV66) U5.H14(VDDSHV41) U5.J14(VDDSHV42) U5.K14(VDDSHV51) U5.L14(VDDSHV52) U5.N5(VDDSHV67) U5.N15(VDDA3P3V_USB0) U5.P5(VDDSHV68) U5.P6(VDDSHV69) U5.P7(VDDSHV11) U5.P8(VDDSHV12) U5.P10(VDDSHV21) U5.P11(VDDSHV22) U5.P12(VDDSHV31) U5.P13(VDDSHV32) U5.R15(VDDA3P3V_USB1) U6.6(C\L\R\) U6.7(P\R\E\) U6.8(VCC) U7.4(VCC) Y4.4(VCC)
VDD_3V3AUX: C18.1 D1.2(A) U2.1(VLDO2) U4.1(EN)
VDD_3V3B: C20.1 C29.1 C126.2 C127.1 C128.1 C129.1 C130.1 C135.1 C153.1 C154.1 C155.2 FB4.1 P2.5(TVDD) P9.3(2) P9.4(27) P10.4(VDD) R11.1 R23.1 R24.1 R101.1 R102.1 R103.1 R104.1 R105.1 R106.1 R107.1 R108.1 R109.1 R110.1 R111.1 R112.2 R113.2 R114.2 R119.1 R150.1 R151.1 R152.1 R153.1 R154.1 R155.1 R157.2 R158.1 R163.1 R166.2 U4.3(OUT) U13.C6(VCCQ4) U13.E6(VCC3) U13.F5(VCC2) U13.J10(VCC0) U13.K9(VCC1) U13.M4(VCCQ5) U13.N4(VCCQ3) U13.P3(VCCQ1) U13.P5(VCCQ2) U14.12(VDDIO) U15.7(2OE) U15.8(VCC)
VDD_5V: C2.2 P1.1 P9.5(3) P9.6(28) U2.10(AC)
VDD_ADC: C93.1 FB2.1 P9.32(41) R27.1 U5.D8(VDDA_ADC)
VDD_CORE: C11.2 C39.2 C40.2 C41.1 C42.1 C43.1 C44.1 C45.1 C46.1 C47.1 C48.1 C49.1 C50.1 C51.1 C52.1 C53.1 C54.1 C55.2 L3.2 U2.29(VDCDC3) U5.F6(VDD_CORE1) U5.F7(VDD_CORE2) U5.G6(VDD_CORE3) U5.G7(VDD_CORE4) U5.G10(VDD_CORE5) U5.H11(VDD_CORE6) U5.J12(VDD_CORE7) U5.K6(VDD_CORE8) U5.K8(VDD_CORE9) U5.K12(VDD_CORE10) U5.L6(VDD_CORE11) U5.L7(VDD_CORE12) U5.L8(VDD_CORE13) U5.L9(VDD_CORE14) U5.M11(VDD_CORE15) U5.M13(VDD_CORE16) U5.N8(VDD_CORE17) U5.N9(VDD_CORE18) U5.N12(VDD_CORE19) U5.N13(VDD_CORE20)
VDD_MPU: C12.2 C62.2 C63.1 C64.1 C65.1 L2.2 U2.24(VDCDC2) U5.F10(VDD_MPU1) U5.F11(VDD_MPU2) U5.F12(VDD_MPU3) U5.F13(VDD_MPU4) U5.G13(VDD_MPU5) U5.H13(VDD_MPU6) U5.J13(VDD_MPU7)
VDD_MPUON: TP2.1(TP) U5.A2(VDD_MPU_MON)
VDD_PHYA: C131.1 C132.1 C133.2 FB4.2 R120.2 R121.2 R122.2 R123.2 R137.2 U14.1(VDD2A) U14.27(VDD1A)
VDD_PLL: C79.1 C92.1 C94.1 C106.1 FB1.2 U5.E7(VDDS_PLL_DDR) U5.H15(VDDS_PLL_MPU) U5.R10(VDDS_PLL_CORE_LCD) U5.R11(VDDS_OSC)
VDD_RTC: C104.1 U5.D6(CAP_VDD_RTC)
VDDS: C80.1 C81.1 C82.1 C83.1 C84.1 C85.1 R8.2 R9.1 U5.E6(VDDS1) U5.E14(VDDS2) U5.F9(VDDS3) U5.K13(VDDS4) U5.N6(VDDS5) U5.P9(VDDS6) U5.P14(VDDS7)
VDDS_DDR: C9.2 C95.2 C96.2 C97.1 C98.1 C99.1 C100.1 C101.1 C102.1 C103.1 C107.1 C108.1 C109.1 C110.1 C111.1 C112.1 C113.1 C114.1 C115.1 C116.1 C117.1 C118.2 C119.1 C120.1 C121.1 C122.2 R6.2 R97.1 R98.1 U5.E5(VDDS_DDR1) U5.F5(VDDS_DDR2) U5.G5(VDDS_DDR3) U5.H5(VDDS_DDR4) U5.J5(VDDS_DDR5) U5.K5(VDDS_DDR6) U5.L5(VDDS_DDR7) U12.A1(VDDQ1) U12.A8(VDDQ2) U12.B2(VDD1) U12.C1(VDDQ3) U12.C9(VDDQ4) U12.D2(VDDQ5) U12.D9(VDD9) U12.E9(VDDQ7) U12.F1(VDDQ8) U12.G7(VDD2) U12.H2(VDDQ9) U12.H9(VDDQ10) U12.K2(VDD4) U12.K8(VDD5) U12.N1(VDD6) U12.N9(VDD7) U12.R1(VDD8) U12.R9(VDD3)
12M_LOOP: U6.2(D) U6.3(Q\)
12MHZ: R21.2 U11.27(OSC_IN)
AIN0: P9.39(20) U5.B6(AIN0)
AIN1: P9.40(45) U5.C7(AIN1)
AIN2: P9.37(19) U5.B7(AIN2)
AIN3: P9.38(44) U5.A7(AIN3)
AIN4: P9.33(17) U5.C8(AIN4)
AIN5: P9.36(43) U5.B8(AIN5)
AIN6: P9.35(18) U5.A8(AIN6)
AIN7: R163.2 R164.1 U5.C9(AIN7)
B_UART0_RX: J1.4 U15.2(1A)
B_UART0_TX: J1.5 U15.3(2Y)
CAP_VBB_MPU: C91.1 U5.C10(CAP_VBB_MPU)
CAP_VDD_SRAM_CORE: C89.1 U5.D9(CAP_VDD_SRAM_CORE)
CAP_VDD_SRAM_MPU: C90.1 U5.D11(CAP_VDD_SRAM_MPU)
CLKOUT2: P2.18(EMU3) P9.41(21) R19.2 R20.1
CLKOUT_SRC: R19.1 U5.D14(EVENT_INTR1/TCLKIN/CLKOUT2/TIME)
CRS: R139.2 U14.14(CRS)
DDR_A0: U5.F3(DDR_A0) U12.N3(A0)
DDR_A1: U5.H1(DDR_A1) U12.P7(A1)
DDR_A2: U5.E4(DDR_A2) U12.P3(A2)
DDR_A3: U5.C3(DDR_A3) U12.N2(A3)
DDR_A4: U5.C2(DDR_A4) U12.P8(A4)
DDR_A5: U5.B1(DDR_A5) U12.P2(A5)
DDR_A6: U5.D5(DDR_A6) U12.R8(A6)
DDR_A7: U5.E2(DDR_A7) U12.R2(A7)
DDR_A8: U5.D4(DDR_A8) U12.T8(A8)
DDR_A9: U5.C1(DDR_A9) U12.R3(A9)
DDR_A10: U5.F4(DDR_A10) U12.L7(A10)
DDR_A11: U5.F2(DDR_A11) U12.R7(A11)
DDR_A12: U5.E3(DDR_A12) U12.N7(A12)
DDR_A13: U5.H3(DDR_A13) U12.T3(A13)
DDR_A14: U5.H4(DDR_A14) U12.T7(A14)
DDR_A15: U5.D3(DDR_A15) U12.M7(A15)
DDR_BA0: U5.C4(DDR_BA0) U12.M2(BA0)
DDR_BA1: U5.E1(DDR_BA1) U12.N8(BA1)
DDR_BA2: U5.B3(DDR_BA2) U12.M3(BA2)
DDR_CASN: U5.F1(DDR_CASN) U12.K3(CASN)
DDR_CKE: R96.2 U5.G3(DDR_CKE) U12.K9(CKE)
DDR_CLK: U5.D2(DDR_CK) U12.J7(CK)
DDR_CLKN: U5.D1(DDR_NCK) U12.K7(CKN)
DDR_CSN: U5.H2(DDR_CSN0) U12.L2(CSN)
DDR_D0: U5.M3(DDR_D0) U12.E3(DQ0)
DDR_D1: U5.M4(DDR_D1) U12.F7(DQ1)
DDR_D2: U5.N1(DDR_D2) U12.F2(DQ2)
DDR_D3: U5.N2(DDR_D3) U12.F8(DQ3)
DDR_D4: U5.N3(DDR_D4) U12.H3(DQ4)
DDR_D5: U5.N4(DDR_D5) U12.H8(DQ5)
DDR_D6: U5.P3(DDR_D6) U12.G2(DQ6)
DDR_D7: U5.P4(DDR_D7) U12.H7(DQ7)
DDR_D8: U5.J1(DDR_D8) U12.D7(DQ8)
DDR_D9: U5.K1(DDR_D9) U12.C3(DQ9)
DDR_D10: U5.K2(DDR_D10) U12.C8(DQ10)
DDR_D11: U5.K3(DDR_D11) U12.C2(DQ11)
DDR_D12: U5.K4(DDR_D12) U12.A7(DQ12)
DDR_D13: U5.L3(DDR_D13) U12.A2(DQ13)
DDR_D14: U5.L4(DDR_D14) U12.B8(DQ14)
DDR_D15: U5.M1(DDR_D15) U12.A3(DQ15)
DDR_DQM0: U5.M2(DDR_DQM0) U12.E7(LDM)
DDR_DQM1: U5.J2(DDR_DQM1) U12.D3(UDM)
DDR_DQS0: U5.P1(DDR_DQS0) U12.F3(LDQS)
DDR_DQS1: U5.L1(DDR_DQS1) U12.C7(UDQS)
DDR_DQSN0: U5.P2(DDR_DQSN0) U12.G3(LDQSN)
DDR_DQSN1: U5.L2(DDR_DQSN1) U12.B7(UDQSN)
DDR_ODT: U5.G1(DDR_ODT) U12.K1(ODT)
DDR_RASN: U5.G4(DDR_RASN) U12.J3(RASN)
DDR_RESETN: R97.2 U5.G2(DDR_RESETN) U12.T2(RESET#)
DDR_VREF: C28.1 C123.1 C124.1 R98.2 R100.1 U5.J4(VREFSSTL) U12.H1(VREF_DQ) U12.M8(VREF_CA)
DDR_VTP: R22.2 U5.J3(DDR_VTP)
DDR_WEN: U5.B2(DDR_WEN) U12.L3(WEN)
DVI_+5V: P6.19(+5V) R146.1 R147.1 RT1.2
EHRPWM1A: P9.14(32) U5.U14(GPMC_A2/GMII2_TXD3/RGMII2_TD3/M)
EHRPWM1B: P9.16(33) U5.T14(GPMC_A3/GMII2_TXD2/RGMII2_TD2/M)
EHRPWM2A: P8.19(10) U5.U10(GPMC_AD8/LCD_DATA23/MMC1_DAT0/M)
EHRPWM2B: P8.13(7) U5.T10(GPMC_AD9/LCD_DATA22/MMC1_DAT1/M)
EMMC_RSTN: R111.2 R162.2 U13.K5(R\S\T\)
EMMC_VCCI: C125.1 U13.C2(VCCI)
ENZ_KALDO_1P8V: R54.2 U5.B4(ENZ_KALDO_1P8V)
ETH_TXD4: R145.1 U14.18(NINT/TXER/TXD4)
GPIO0_7: P9.42(46) R50.1 R51.1
GPIO0_7SRC: R50.2 U5.C18(ECAP0_IN_PWM0_OUT/UART3_TXD/SPI)
GPIO0_26: P8.14(32) U5.T11(GPMC_AD10/LCD_DATA21/MMC1_DAT2/)
GPIO0_27: P8.17(9) U5.U12(GPMC_AD11/LCD_DATA20/MMC1_DAT3/)
GPIO1_12: P8.12(31) U5.T12(GPMC_AD12/LCD_DATA19/MMC1_DAT4/)
GPIO1_13: P8.11(6) U5.R12(GPMC_AD13/LCD_DATA18/MMC1_DAT5/)
GPIO1_14: P8.16(33) U5.V13(GPMC_AD14/LCD_DATA17/MMC1_DAT6/)
GPIO1_15: P8.15(8) U5.U13(GPMC_AD15/LCD_DATA16/MMC1_DAT7/)
GPIO1_16: P9.15(8) R160.2 R161.2
GPIO1_17: P9.23(12) U5.V14(GPMC_A1/GMII2_RXDV/RGMII2_RCTL/)
GPIO1_28: P9.12(31) U5.U18(GPMC_BE1N/GMII2_COL/GPMC_CSN6/M)
GPIO1_29: P8.26(38) U5.V6(GPMC_CSN0/GPIO1_29)
GPIO2_1: P8.18(34) U5.V12(GPMC_CLK/LCD_MEM_CLK/GPMC_WAIT1)
GPIO3_18: R51.2 U5.B12(MCASP0_ACLKR/EQEP0A_IN/MCASP0_A)
GPIO3_19: P9.27(14) U5.C13(MCASP0_FSR/EQEP0B_IN/MCASP0_AXR)
GPIO3_20: R20.2 U5.D13(MCASP0_AXR1/EQEP0_INDEX//MCASP1)
GPIO3_21: P9.25(13) R167.2 U5.A14(MCASP0_AHCLKX/EQEP0_STROBE/MCAS)
GRN_C: P5.10(GRNC) R132.2
GRNA: P5.9(GRNA) U14.3(LED1/REGOFF)
HDMI_1V8: C144.1 C145.1 C146.1 C147.1 C148.1 C149.1 C150.1 C151.1 FB5.1 U11.5(VDDDC0(1.8V)) U11.14(VDDIOA(1.8V)) U11.29(VDDDC1(1.8V)) U11.35(VDDA0(1.8V)) U11.36(VDDA1(TX)(1.8V)) U11.41(VDDA2(TX)(1.8V)) U11.46(VDDA3(TX)(1.8V)) U11.47(VDDA(PLL0)(1.8V)) U11.48(VDDA(PLL1)(1.8V)) U11.55(VDDIOB(1.8V))
HDMI_CEC: D8.1(CATHODE) P6.15(CEC) U11.30(CEC)
HDMI_CEC_D: D8.2(ANODE) R166.1
HDMI_DSCL: P6.17(SCL) R146.2 U11.33(DSCL)
HDMI_DSDA: P6.18(SDA) R147.2 U11.32(DSDA)
HDMI_HPD: P6.1(HPLG) U11.31(HPD)
HDMI_INT: R158.2 U5.U16(GPMC_A9/GMII2_RXD2/RGMII2_RD2/M) U11.50(INT)
HDMI_SWING: R148.1 U11.34(EXT_SWING)
HDMI_TX0+: D6.2 P6.9(DAT0+) U11.40(TX0+)
HDMI_TX0-: D6.1 P6.11(DAT0-) U11.39(TX0-)
HDMI_TX1+: D7.5 P6.6(DAT1+) U11.43(TX1+)
HDMI_TX1-: D7.4 P6.8(DAT1-) U11.42(TX1-)
HDMI_TX2+: D7.2 P6.3(DAT2+) U11.45(TX2+)
HDMI_TX2-: D7.1 P6.5(DAT2-) U11.44(TX2-)
HDMI_TXC+: D6.4 P6.12(CLK+) U11.38(TXC+)
HDMI_TXC-: D6.5 P6.14(CLK-) U11.37(TXC-)
HDMICLK_DISN: U5.V17(GPMC_A11/GMII2_RXD0/RGMII2_RD0/) Y4.1(OE)
I2C0_SCL: R3.2 U2.28(SCL) U5.C16(I2C0_SCL/TIMER7/UART2_RTSN/ECAP) U7.1(SCL) U11.52(CSCL)
